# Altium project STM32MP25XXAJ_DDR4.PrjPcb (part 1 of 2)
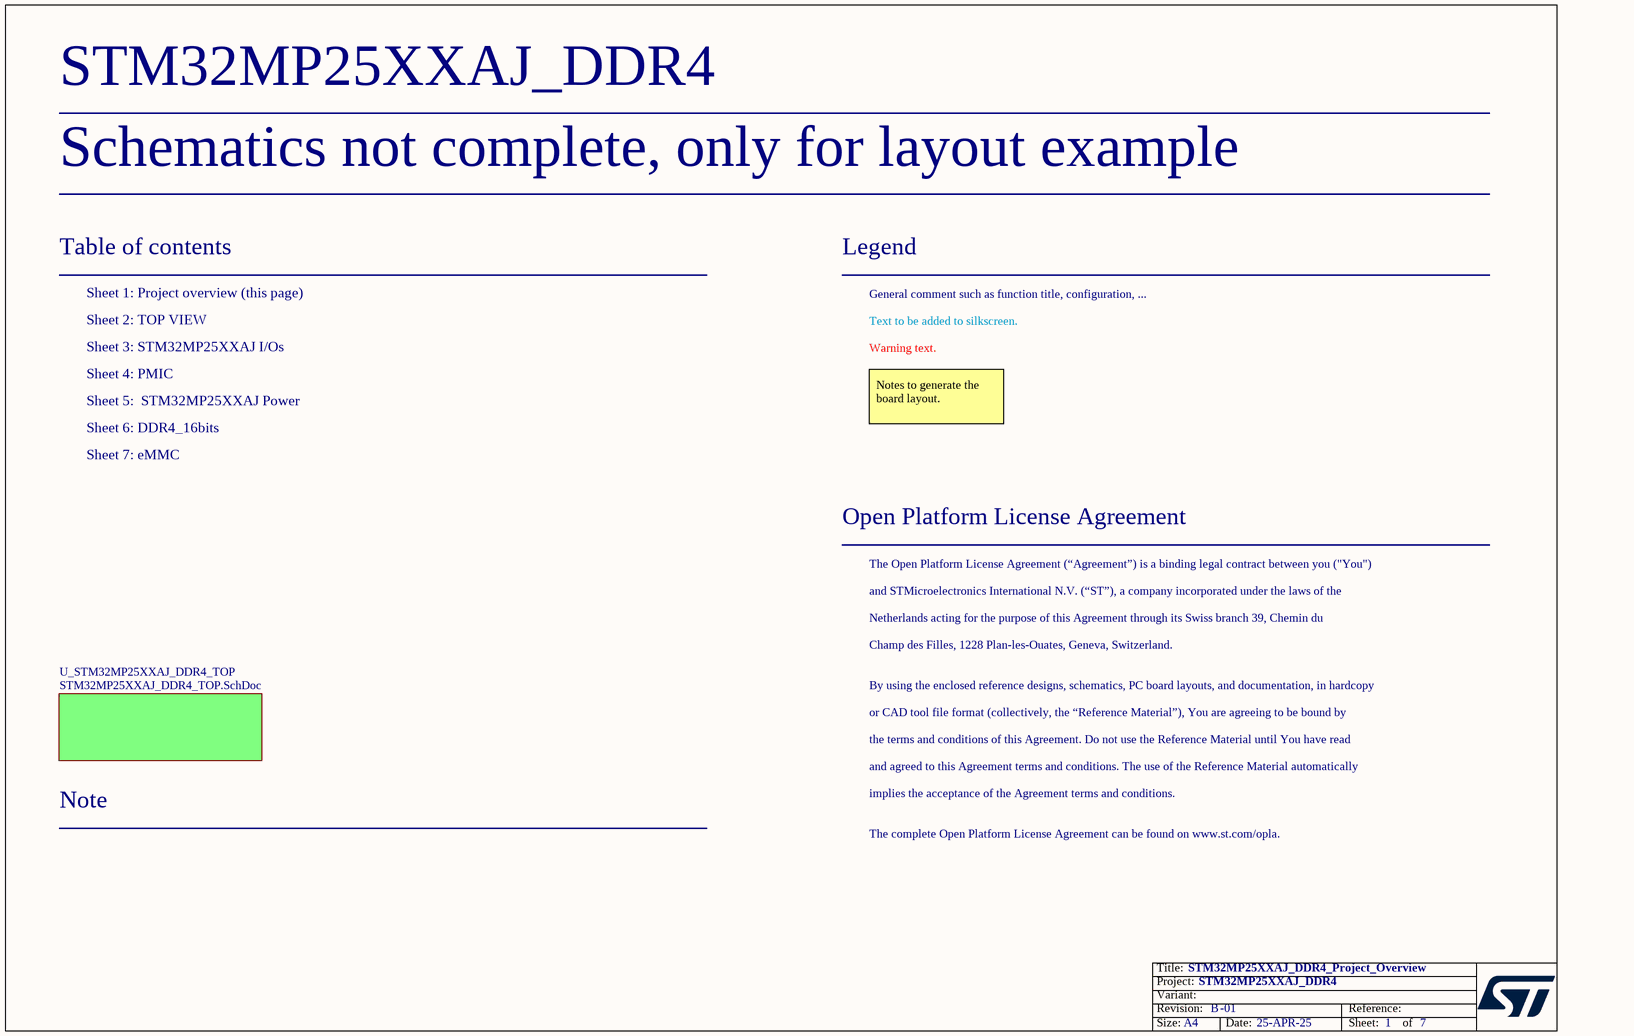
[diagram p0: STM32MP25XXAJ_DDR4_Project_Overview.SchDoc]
Board_Assembly_Revision: 01; Board_Document_Date: 25-APR-25; Board_Name: STM32MP25XXAJ_DDR4; Board_PCB_Revision: B
7 sheets, 226 parts. Net scope: flat (ports and power ports of the same name join across sheets).
Board file: STM32MP25XXAJ_DDR4.PcbDoc
Sheets:
  STM32MP25XXAJ_DDR4_Project_Overview.SchDoc
    U_STM32MP25XXAJ_DDR4_TOP = STM32MP25XXAJ_DDR4_TOP.SchDoc
      U_STM32MP25XXAJ I_Os = STM32MP25XXAJ I_Os.SchDoc
      U_PMIC = PMIC.SchDoc
      U_STM32MP25XXAJ Power = STM32MP25XXAJ Power.SchDoc
      U_eMMC = eMMC.SchDoc
      U_DDR4_16bits = DDR4_16bits.SchDoc

## Sheet STM32MP25XXAJ_DDR4_Project_Overview.SchDoc: STM32MP25XXAJ_DDR4_Project_Overview
size A4; Date: Not used; ApprovedBy: Not used; CheckedBy: Not used; Author: Not used; CompanyName: STMicroelectronics; DrawnBy: Not used; Engineer: Not used; Organization: Not used; Address1: Not used; Address2: Not used; Address3: Not used; Address4: Not used; DocumentNumber: 1; Revision: Not used; SheetNumber: 1; SheetTotal: 7

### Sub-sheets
U_STM32MP25XXAJ_DDR4_TOP = STM32MP25XXAJ_DDR4_TOP.SchDoc: no entries

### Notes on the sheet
- Schematics not complete, only for layout example
- Table of contents
- Sheet 1: Project overview (this page)
- Legend
- General comment such as function title, configuration, ...
- Sheet 2: TOP VIEW
- Sheet 3: STM32MP25XXAJ I/Os
- Sheet 4: PMIC
- Text to be added to silkscreen.
- Warning text.
- Sheet 5:  STM32MP25XXAJ Power
- Sheet 6: DDR4_16bits
- Notes to generate the board layout.
- Sheet 7: eMMC
- Open Platform License Agreement
- The Open Platform License Agreement (“Agreement”) is a binding legal contract between you ("You")
- and STMicroelectronics International N.V. (“ST”), a company incorporated under the laws of the
- Netherlands acting for the purpose of this Agreement through its Swiss branch 39, Chemin du
- Champ des Filles, 1228 Plan-les-Ouates, Geneva, Switzerland.
- By using the enclosed reference designs, schematics, PC board layouts, and documentation, in hardcopy
- or CAD tool file format (collectively, the “Reference Material”), You are agreeing to be bound by
- the terms and conditions of this Agreement. Do not use the Reference Material until You have read
- and agreed to this Agreement terms and conditions. The use of the Reference Material automatically
- Note
- implies the acceptance of the Agreement terms and conditions.
- The complete Open Platform License Agreement can be found on www.st.com/opla.

## Sheet STM32MP25XXAJ_DDR4_TOP.SchDoc: TOP
size A4; Date: Not used; ApprovedBy: Not used; CheckedBy: Not used; Author: Not used; CompanyName: STMicroelectronics; DrawnBy: Not used; Engineer: Not used; Organization: Not used; Address1: Not used; Address2: Not used; Address3: Not used; Address4: Not used; DocumentNumber: 2; Revision: Not used; SheetNumber: 2; SheetTotal: 7
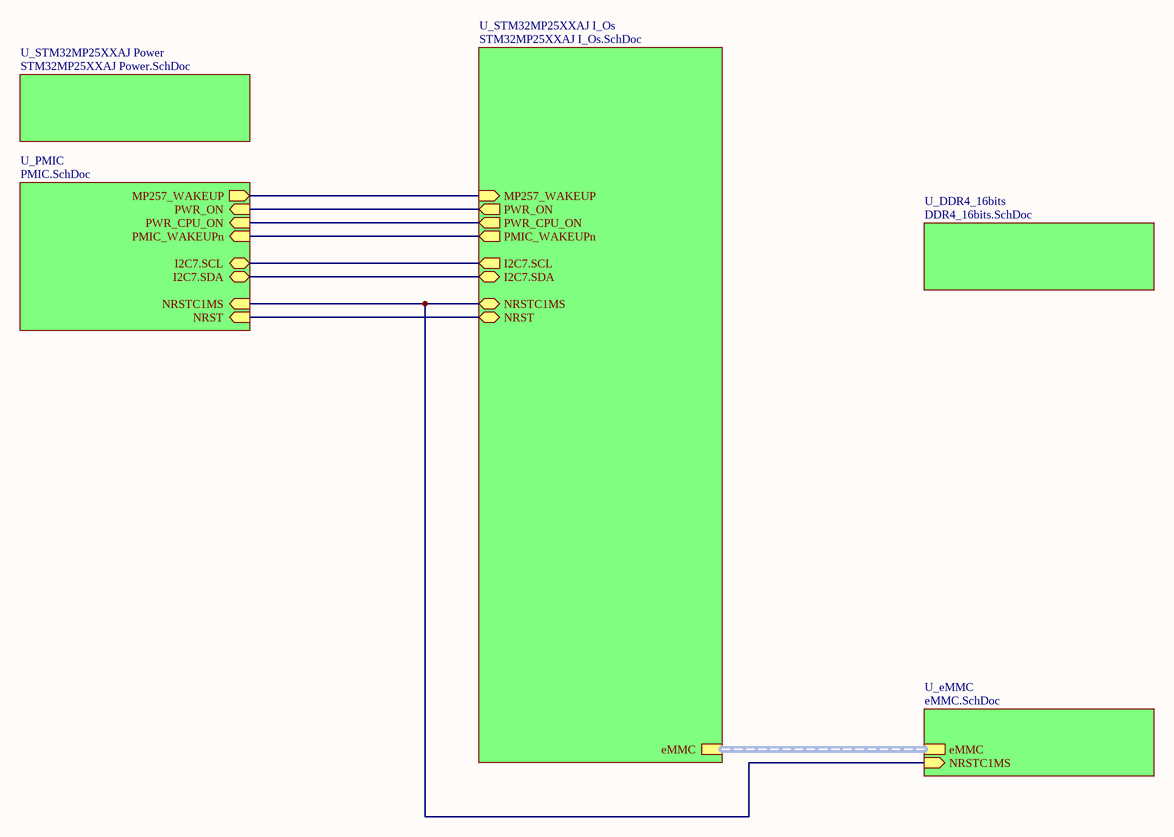
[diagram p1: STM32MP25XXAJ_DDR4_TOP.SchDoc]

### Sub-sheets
U_DDR4_16bits = DDR4_16bits.SchDoc: no entries
U_eMMC = eMMC.SchDoc: eMMC (harness eMMC), NRSTC1MS (in)
U_PMIC = PMIC.SchDoc: PMIC_WAKEUPn (in), NRST (in), I2C7.SCL (bidir), PWR_ON (in), PWR_CPU_ON (in), NRSTC1MS (in), I2C7.SDA (bidir), MP257_WAKEUP (out)
U_STM32MP25XXAJ I_Os = STM32MP25XXAJ I_Os.SchDoc: NRST (bidir), PWR_ON (out), NRSTC1MS (bidir), I2C7.SDA (bidir), I2C7.SCL (out), PWR_CPU_ON (out), MP257_WAKEUP (in), PMIC_WAKEUPn (out), eMMC (harness eMMC)
U_STM32MP25XXAJ Power = STM32MP25XXAJ Power.SchDoc: no entries

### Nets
(unnamed): sheet U_STM32MP25XXAJ I_Os/NRST, sheet U_PMIC/NRST
(unnamed): sheet U_STM32MP25XXAJ I_Os/PWR_ON, sheet U_PMIC/PWR_ON  [a separate net that carries the same name]
(unnamed): sheet U_STM32MP25XXAJ I_Os/NRSTC1MS, sheet U_PMIC/NRSTC1MS, sheet U_eMMC/NRSTC1MS  [a separate net that carries the same name]
(unnamed): sheet U_STM32MP25XXAJ I_Os/I2C7.SDA, sheet U_PMIC/I2C7.SDA  [a separate net that carries the same name]
(unnamed): sheet U_STM32MP25XXAJ I_Os/I2C7.SCL, sheet U_PMIC/I2C7.SCL  [a separate net that carries the same name]
(unnamed): sheet U_STM32MP25XXAJ I_Os/PWR_CPU_ON, sheet U_PMIC/PWR_CPU_ON  [a separate net that carries the same name]
(unnamed): sheet U_STM32MP25XXAJ I_Os/MP257_WAKEUP, sheet U_PMIC/MP257_WAKEUP  [a separate net that carries the same name]
(unnamed): sheet U_STM32MP25XXAJ I_Os/PMIC_WAKEUPn, sheet U_PMIC/PMIC_WAKEUPn  [a separate net that carries the same name]

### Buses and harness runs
harness sheet U_eMMC/eMMC = sheet U_STM32MP25XXAJ I_Os/eMMC

## Sheet STM32MP25XXAJ I_Os.SchDoc: STM32MP25XXAJ  I/Os
size A3; Date: Not used; ApprovedBy: Not used; CheckedBy: Not used; Author: Not used; CompanyName: STMicroelectronics; DrawnBy: Not used; Engineer: Not used; Organization: Not used; Address1: Not used; Address2: Not used; Address3: Not used; Address4: Not used; DocumentNumber: 3; Revision: Not used; SheetNumber: 3; SheetTotal: 7
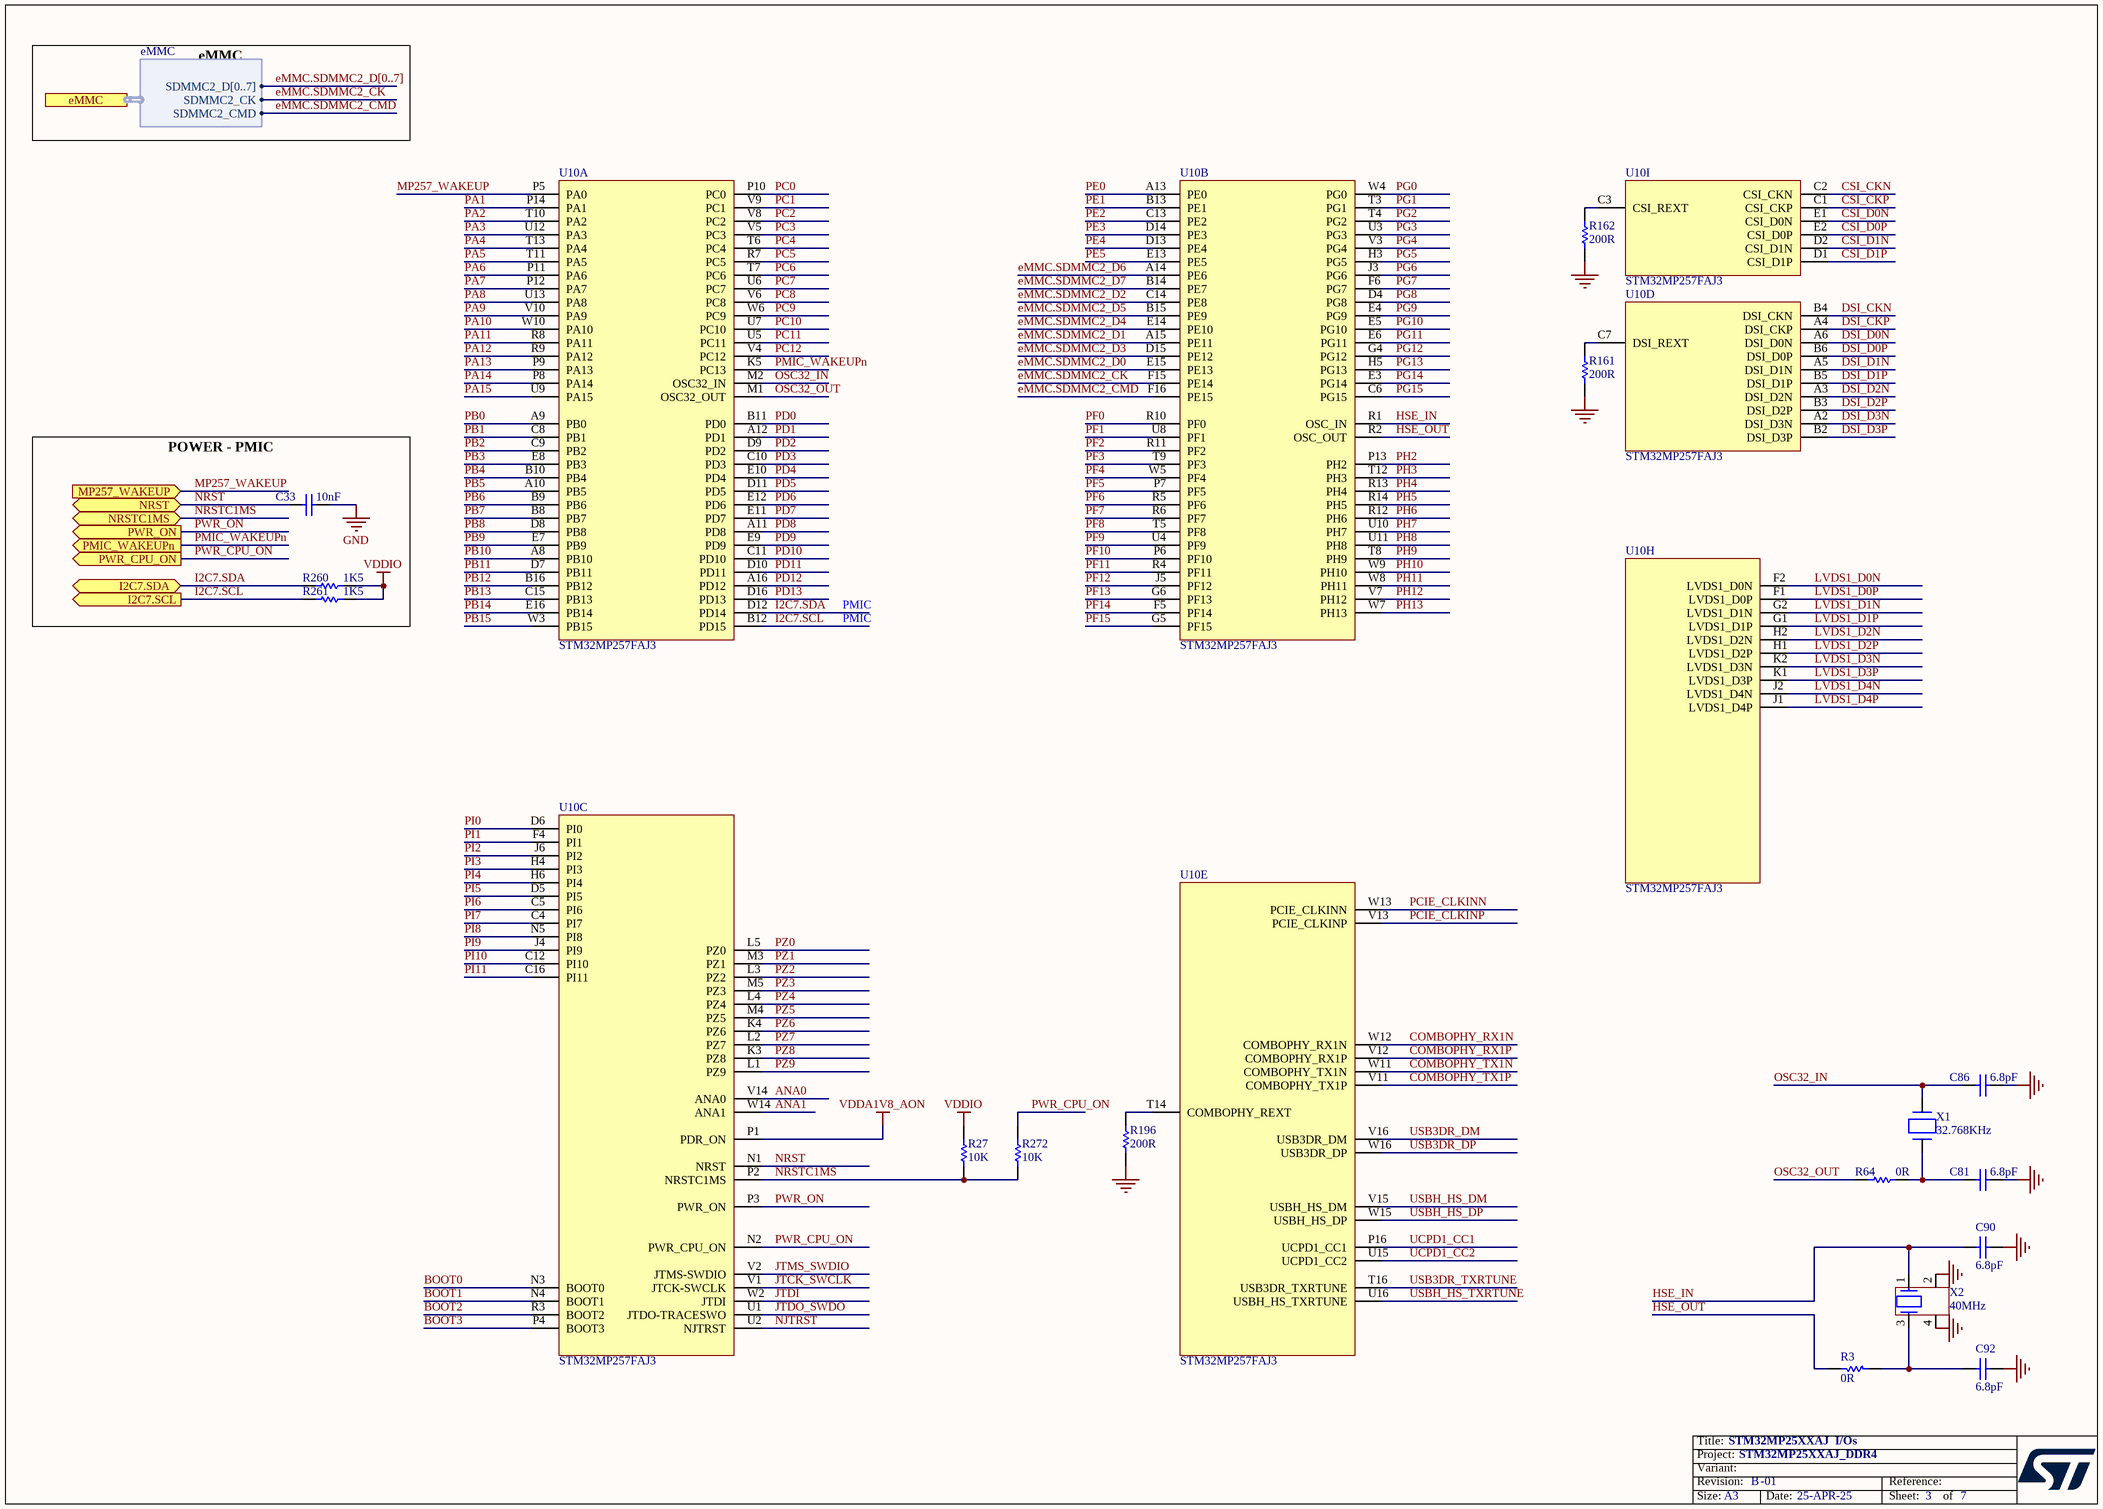
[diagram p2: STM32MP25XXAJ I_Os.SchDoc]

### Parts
C33  value 10nF  [C0402]  (hidden comment: Capacitor)
C81  value 6.8pF  [C0402]  (hidden comment: Capacitor)
C86  value 6.8pF  [C0402]  (hidden comment: Capacitor)
C90  value 6.8pF  [C0402]  (hidden comment: Capacitor)
C92  value 6.8pF  [C0402]  (hidden comment: Capacitor)
R3  value 0R  [R0402]
R27  value 10K  [R0402]  (hidden comment: Resistor)
R64  value 0R  [R0402]
R161  value 200R  [R0402]  (hidden comment: Resistor)
R162  value 200R  [R0402]  (hidden comment: Resistor)
R196  value 200R  [R0402]  (hidden comment: Resistor)
R260  value 1K5  [R0402]  (hidden comment: Resistor)
R261  value 1K5  [R0402]  (hidden comment: Resistor)
R272  value 10K  [R0402]  (hidden comment: Resistor)
U10  value STM32MP257FAJ3  [ICC_TFBGA361_16X16_P080]  (hidden comment: IC_STM32MP257FAJ3)  (parts A,B,C,D,E,H,I of 9)
X1  value 32.768KHz  [CRY_NX2012SA_2P]  (hidden comment: XTAL_2_PINS)
X2  value 40MHz  [CRY_NX1612SA_4P]  (hidden comment: XTAL_4_PINS)

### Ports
eMMC (harness eMMC), I2C7.SCL (out), I2C7.SDA (bidir), MP257_WAKEUP (in), NRST (bidir), NRSTC1MS (bidir), PMIC_WAKEUPn (out), PWR_CPU_ON (out), PWR_ON (out)

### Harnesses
eMMC: SDMMC2_CK, SDMMC2_CMD, SDMMC2_D[0..7]

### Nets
GND: C33.1 C81.2 C86.2 C90.1 C92.2 R161.2 R162.2 R196.1 X2.2 X2.4
VDDA1V8_AON: U10.P1(PDR_ON)
VDDIO: R27.2 R260.2 R261.2
ANA0: U10.V14(ANA0)
ANA1: U10.W14(ANA1)
BOOT0: U10.N3(BOOT0)
BOOT1: U10.N4(BOOT1)
BOOT2: U10.R3(BOOT2)
BOOT3: U10.P4(BOOT3)
COMBOPHY_RX1N: U10.W12(COMBOPHY_RX1N)
COMBOPHY_RX1P: U10.V12(COMBOPHY_RX1P)
COMBOPHY_TX1N: U10.W11(COMBOPHY_TX1N)
COMBOPHY_TX1P: U10.V11(COMBOPHY_TX1P)
CSI_CKN: U10.C2(CSI_CKN)
CSI_CKP: U10.C1(CSI_CKP)
CSI_D0N: U10.E1(CSI_D0N)
CSI_D0P: U10.E2(CSI_D0P)
CSI_D1N: U10.D2(CSI_D1N)
CSI_D1P: U10.D1(CSI_D1P)
DSI_CKN: U10.B4(DSI_CKN)
DSI_CKP: U10.A4(DSI_CKP)
DSI_D0N: U10.A6(DSI_D0N)
DSI_D0P: U10.B6(DSI_D0P)
DSI_D1N: U10.A5(DSI_D1N)
DSI_D1P: U10.B5(DSI_D1P)
DSI_D2N: U10.A3(DSI_D2N)
DSI_D2P: U10.B3(DSI_D2P)
DSI_D3N: U10.A2(DSI_D3N)
DSI_D3P: U10.B2(DSI_D3P)
eMMC.SDMMC2_CK: U10.F15(PE14) ; port eMMC.SDMMC2_CK
eMMC.SDMMC2_CMD: U10.F16(PE15) ; port eMMC.SDMMC2_CMD
eMMC.SDMMC2_D0: U10.E15(PE13)
eMMC.SDMMC2_D1: U10.A15(PE11)
eMMC.SDMMC2_D2: U10.C14(PE8)
eMMC.SDMMC2_D3: U10.D15(PE12)
eMMC.SDMMC2_D4: U10.E14(PE10)
eMMC.SDMMC2_D5: U10.B15(PE9)
eMMC.SDMMC2_D6: U10.A14(PE6)
eMMC.SDMMC2_D7: U10.B14(PE7)
HSE_IN: C90.2 U10.R1(OSC_IN) X2.1
HSE_OUT: R3.2 U10.R2(OSC_OUT)
I2C7.SCL: R261.1 U10.B12(PD15) ; port I2C7.SCL
I2C7.SDA: R260.1 U10.D12(PD14) ; port I2C7.SDA
JTCK_SWCLK: U10.V1(JTCK-SWCLK)
JTDI: U10.W2(JTDI)
JTDO_SWDO: U10.U1(JTDO-TRACESWO)
JTMS_SWDIO: U10.V2(JTMS-SWDIO)
LVDS1_D0N: U10.F2(LVDS1_D0N)
LVDS1_D0P: U10.F1(LVDS1_D0P)
LVDS1_D1N: U10.G2(LVDS1_D1N)
LVDS1_D1P: U10.G1(LVDS1_D1P)
LVDS1_D2N: U10.H2(LVDS1_D2N)
LVDS1_D2P: U10.H1(LVDS1_D2P)
LVDS1_D3N: U10.K2(LVDS1_D3N)
LVDS1_D3P: U10.K1(LVDS1_D3P)
LVDS1_D4N: U10.J2(LVDS1_D4N)
LVDS1_D4P: U10.J1(LVDS1_D4P)
MP257_WAKEUP: U10.P5(PA0) ; port MP257_WAKEUP
NJTRST: U10.U2(NJTRST)
NRST: C33.2 U10.N1(NRST) ; port NRST
NRSTC1MS: R27.1 R272.1 U10.P2(NRSTC1MS) ; port NRSTC1MS
OSC32_IN: C86.1 U10.M2(OSC32_IN) X1.2(X2)
OSC32_OUT: R64.1 U10.M1(OSC32_OUT)
PA1: U10.P14(PA1)
PA2: U10.T10(PA2)
PA3: U10.U12(PA3)
PA4: U10.T13(PA4)
PA5: U10.T11(PA5)
PA6: U10.P11(PA6)
PA7: U10.P12(PA7)
PA8: U10.U13(PA8)
PA9: U10.V10(PA9)
PA10: U10.W10(PA10)
PA11: U10.R8(PA11)
PA12: U10.R9(PA12)
PA13: U10.P9(PA13)
PA14: U10.P8(PA14)
PA15: U10.U9(PA15)
PB0: U10.A9(PB0)
PB1: U10.C8(PB1)
PB2: U10.C9(PB2)
PB3: U10.E8(PB3)
PB4: U10.B10(PB4)
PB5: U10.A10(PB5)
PB6: U10.B9(PB6)
PB7: U10.B8(PB7)
PB8: U10.D8(PB8)
PB9: U10.E7(PB9)
PB10: U10.A8(PB10)
PB11: U10.D7(PB11)
PB12: U10.B16(PB12)
PB13: U10.C15(PB13)
PB14: U10.E16(PB14)
PB15: U10.W3(PB15)
PC0: U10.P10(PC0)
PC1: U10.V9(PC1)
PC2: U10.V8(PC2)
PC3: U10.V5(PC3)
PC4: U10.T6(PC4)
PC5: U10.R7(PC5)
PC6: U10.T7(PC6)
PC7: U10.U6(PC7)
PC8: U10.V6(PC8)
PC9: U10.W6(PC9)
PC10: U10.U7(PC10)
PC11: U10.U5(PC11)
PC12: U10.V4(PC12)
PCIE_CLKINN: U10.W13(PCIE_CLKINN)
PCIE_CLKINP: U10.V13(PCIE_CLKINP)
PD0: U10.B11(PD0)
PD1: U10.A12(PD1)
PD2: U10.D9(PD2)
PD3: U10.C10(PD3)
PD4: U10.E10(PD4)
PD5: U10.D11(PD5)
PD6: U10.E12(PD6)
PD7: U10.E11(PD7)
PD8: U10.A11(PD8)
PD9: U10.E9(PD9)
PD10: U10.C11(PD10)
PD11: U10.D10(PD11)
PD12: U10.A16(PD12)
PD13: U10.D16(PD13)
PE0: U10.A13(PE0)
PE1: U10.B13(PE1)
PE2: U10.C13(PE2)
PE3: U10.D14(PE3)
PE4: U10.D13(PE4)
PE5: U10.E13(PE5)
PF0: U10.R10(PF0)
PF1: U10.U8(PF1)
PF2: U10.R11(PF2)
PF3: U10.T9(PF3)
PF4: U10.W5(PF4)
PF5: U10.P7(PF5)
PF6: U10.R5(PF6)
PF7: U10.R6(PF7)
PF8: U10.T5(PF8)
PF9: U10.U4(PF9)
PF10: U10.P6(PF10)
PF11: U10.R4(PF11)
PF12: U10.J5(PF12)
PF13: U10.G6(PF13)
PF14: U10.F5(PF14)
PF15: U10.G5(PF15)
PG0: U10.W4(PG0)
PG1: U10.T3(PG1)
PG2: U10.T4(PG2)
PG3: U10.U3(PG3)
PG4: U10.V3(PG4)
PG5: U10.H3(PG5)
PG6: U10.J3(PG6)
PG7: U10.F6(PG7)
PG8: U10.D4(PG8)
PG9: U10.E4(PG9)
PG10: U10.E5(PG10)
PG11: U10.E6(PG11)
PG12: U10.G4(PG12)
PG13: U10.H5(PG13)
PG14: U10.E3(PG14)
PG15: U10.C6(PG15)
PH2: U10.P13(PH2)
PH3: U10.T12(PH3)
PH4: U10.R13(PH4)
PH5: U10.R14(PH5)
PH6: U10.R12(PH6)
PH7: U10.U10(PH7)
PH8: U10.U11(PH8)
PH9: U10.T8(PH9)
PH10: U10.W9(PH10)
PH11: U10.W8(PH11)
PH12: U10.V7(PH12)
PH13: U10.W7(PH13)
PI0: U10.D6(PI0)
PI1: U10.F4(PI1)
PI2: U10.J6(PI2)
PI3: U10.H4(PI3)
PI4: U10.H6(PI4)
PI5: U10.D5(PI5)
PI6: U10.C5(PI6)
PI7: U10.C4(PI7)
PI8: U10.N5(PI8)
PI9: U10.J4(PI9)
PI10: U10.C12(PI10)
PI11: U10.C16(PI11)
PMIC_WAKEUPn: U10.K5(PC13) ; port PMIC_WAKEUPn
PWR_CPU_ON: R272.2 U10.N2(PWR_CPU_ON) ; port PWR_CPU_ON
PWR_ON: U10.P3(PWR_ON) ; port PWR_ON
PZ0: U10.L5(PZ0)
PZ1: U10.M3(PZ1)
PZ2: U10.L3(PZ2)
PZ3: U10.M5(PZ3)
PZ4: U10.L4(PZ4)
PZ5: U10.M4(PZ5)
PZ6: U10.K4(PZ6)
PZ7: U10.L2(PZ7)
PZ8: U10.K3(PZ8)
PZ9: U10.L1(PZ9)
UCPD1_CC1: U10.P16(UCPD1_CC1)
UCPD1_CC2: U10.U15(UCPD1_CC2)
USB3DR_DM: U10.V16(USB3DR_DM)
USB3DR_DP: U10.W16(USB3DR_DP)
USB3DR_TXRTUNE: U10.T16(USB3DR_TXRTUNE)
USBH_HS_DM: U10.V15(USBH_HS_DM)
USBH_HS_DP: U10.W15(USBH_HS_DP)
USBH_HS_TXRTUNE: U10.U16(USBH_HS_TXRTUNE)
NetC81_1: C81.1 R64.2 X1.1(X1)
NetC92_1: C92.1 R3.1 X2.3
NetR161_1: R161.1 U10.C7(DSI_REXT)
NetR162_1: R162.1 U10.C3(CSI_REXT)
NetR196_2: R196.2 U10.T14(COMBOPHY_REXT)

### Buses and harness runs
bus eMMC.SDMMC2_D[0..7]

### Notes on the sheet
- eMMC
- POWER - PMIC
- PMIC

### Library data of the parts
C33 = MCD-00011: Capacitor, MLCC, 10nF, 16V, X7R, 10%, 0402, T=0.5mm; Manufacturer_Part_Number: CC0402KRX7R7BB103; Manufacturer: YAGEO; Provided_By: SUBCO; Initial_Board_Reference: MB1274
C81 C86 = MCD-00674: Capacitor, MLCC, 6.8pF, 50V, NPO, +-0.25pF, 0402, T=0.5mm; Manufacturer_Part_Number: CC0402CRNPO9BN6R8; Manufacturer: YAGEO; Part_Preference: Recommended; Provided_By: SUBCO; Initial_Board_Reference: MB1319; Path: ws/MCD_ApplicationBoards/Lists/MCDPARTSdatabase; Item Type: Item; Component_Country_Of_Origin: China; ID: 3068; ShowFields: YES
C90 C92 = MCD-00674: Capacitor, MLCC, 6.8pF, 50V, NPO, +-0.25pF, 0402, T=0.5mm; Manufacturer_Part_Number: CC0402CRNPO9BN6R8; Manufacturer: YAGEO; Part_Preference: Recommended; Provided_By: SUBCO; Initial_Board_Reference: MB1319; Component_Country_Of_Origin: China; ID: 3068; ShowFields: YES
R3 R64 = MCD-00052: Resistor,0R,0402,5%,1/16W; Manufacturer_Part_Number: RC0402JR-070RL; Manufacturer: YAGEO; Part_Preference: Recommended; Provided_By: SUBCO; Initial_Board_Reference: mb1274; Order_Code_RS: 618-5804; Component_Country_Of_Origin: China; ID: 2540; ShowFields: YES
R27 R272 = MCD-00053: Resistor,10K,0402,1%,1/16W; BMS_Part_Number: 9131590; Part_Preference: Recommended; Manufacturer: YAGEO; Manufacturer_Part_Number: RC0402FR-0710KL; Component_Country_Of_Origin: China; ID: 2539; ShowFields: YES
R161 R162 = MCD-00417: Resistor,200R,0402,1%,1/16W; Manufacturer_Part_Number: RC0402FR-07200RL; Manufacturer: YAGEO; Part_Preference: Recommended; ECCN_US: EAR99; ECCN_EU: NEC; Provided_By: SUBCO
R196 = MCD-00417: Resistor,200R,0402,1%,1/16W; Part_Preference: Recommended; Manufacturer: YAGEO; Manufacturer_Part_Number: RC0402FR-07200RL
R260 R261 = MCD-00068: Resistor,1K5,0402,1%,1/16W; Part_Preference: Recommended; Manufacturer: YAGEO; Manufacturer_Part_Number: RC0402FR-071K5L; Component_Country_Of_Origin: China; ID: 2524; ShowFields: YES
U10 = MCD-04441: MPU, Dual Core ARM cortex-A35 64-bit + M33 32-bit,  808KB SRAM, With Crypto; Part_Type: IC; Part_Preference: Recommended; Manufacturer: STMICROELECTRONICS; ShowFields: YES; ID: 6557
X1 = MCD-01479: Crystal, 32.768kHz, 6pF, +/-20ppm, 80K, 2.05x1.2mm; BMS_Part_Number: 9157049; Part_Type: Crystal_Osc; Part_Preference: Recommended; Manufacturer: NDK; Manufacturer_Part_Number: NX2012SA-32.768KHZ-EXS00A-MU00527; Component_Country_Of_Origin: Unknown; ShowFields: YES; ID: 3579
X2 = MCD-02344: Crystal, 40MHz, 6pF, +/-20ppm, 80R, 1.6x1.2mm; Part_Type: Crystal_Osc; Part_Preference: Recommended; Manufacturer: NDK; Manufacturer_Part_Number: NX1612SA-40MHZ-EXS00A-CS13836; Component_Country_Of_Origin: Unknown; ShowFields: YES; ID: 4450

## Sheet PMIC.SchDoc: PMIC
size A3; Date: Not used; ApprovedBy: Not used; CheckedBy: Not used; Author: Not used; CompanyName: STMicroelectronics; DrawnBy: Not used; Engineer: Not used; Organization: Not used; Address1: Not used; Address2: Not used; Address3: Not used; Address4: Not used; DocumentNumber: 4; Revision: Not used; SheetNumber: 4; SheetTotal: 7
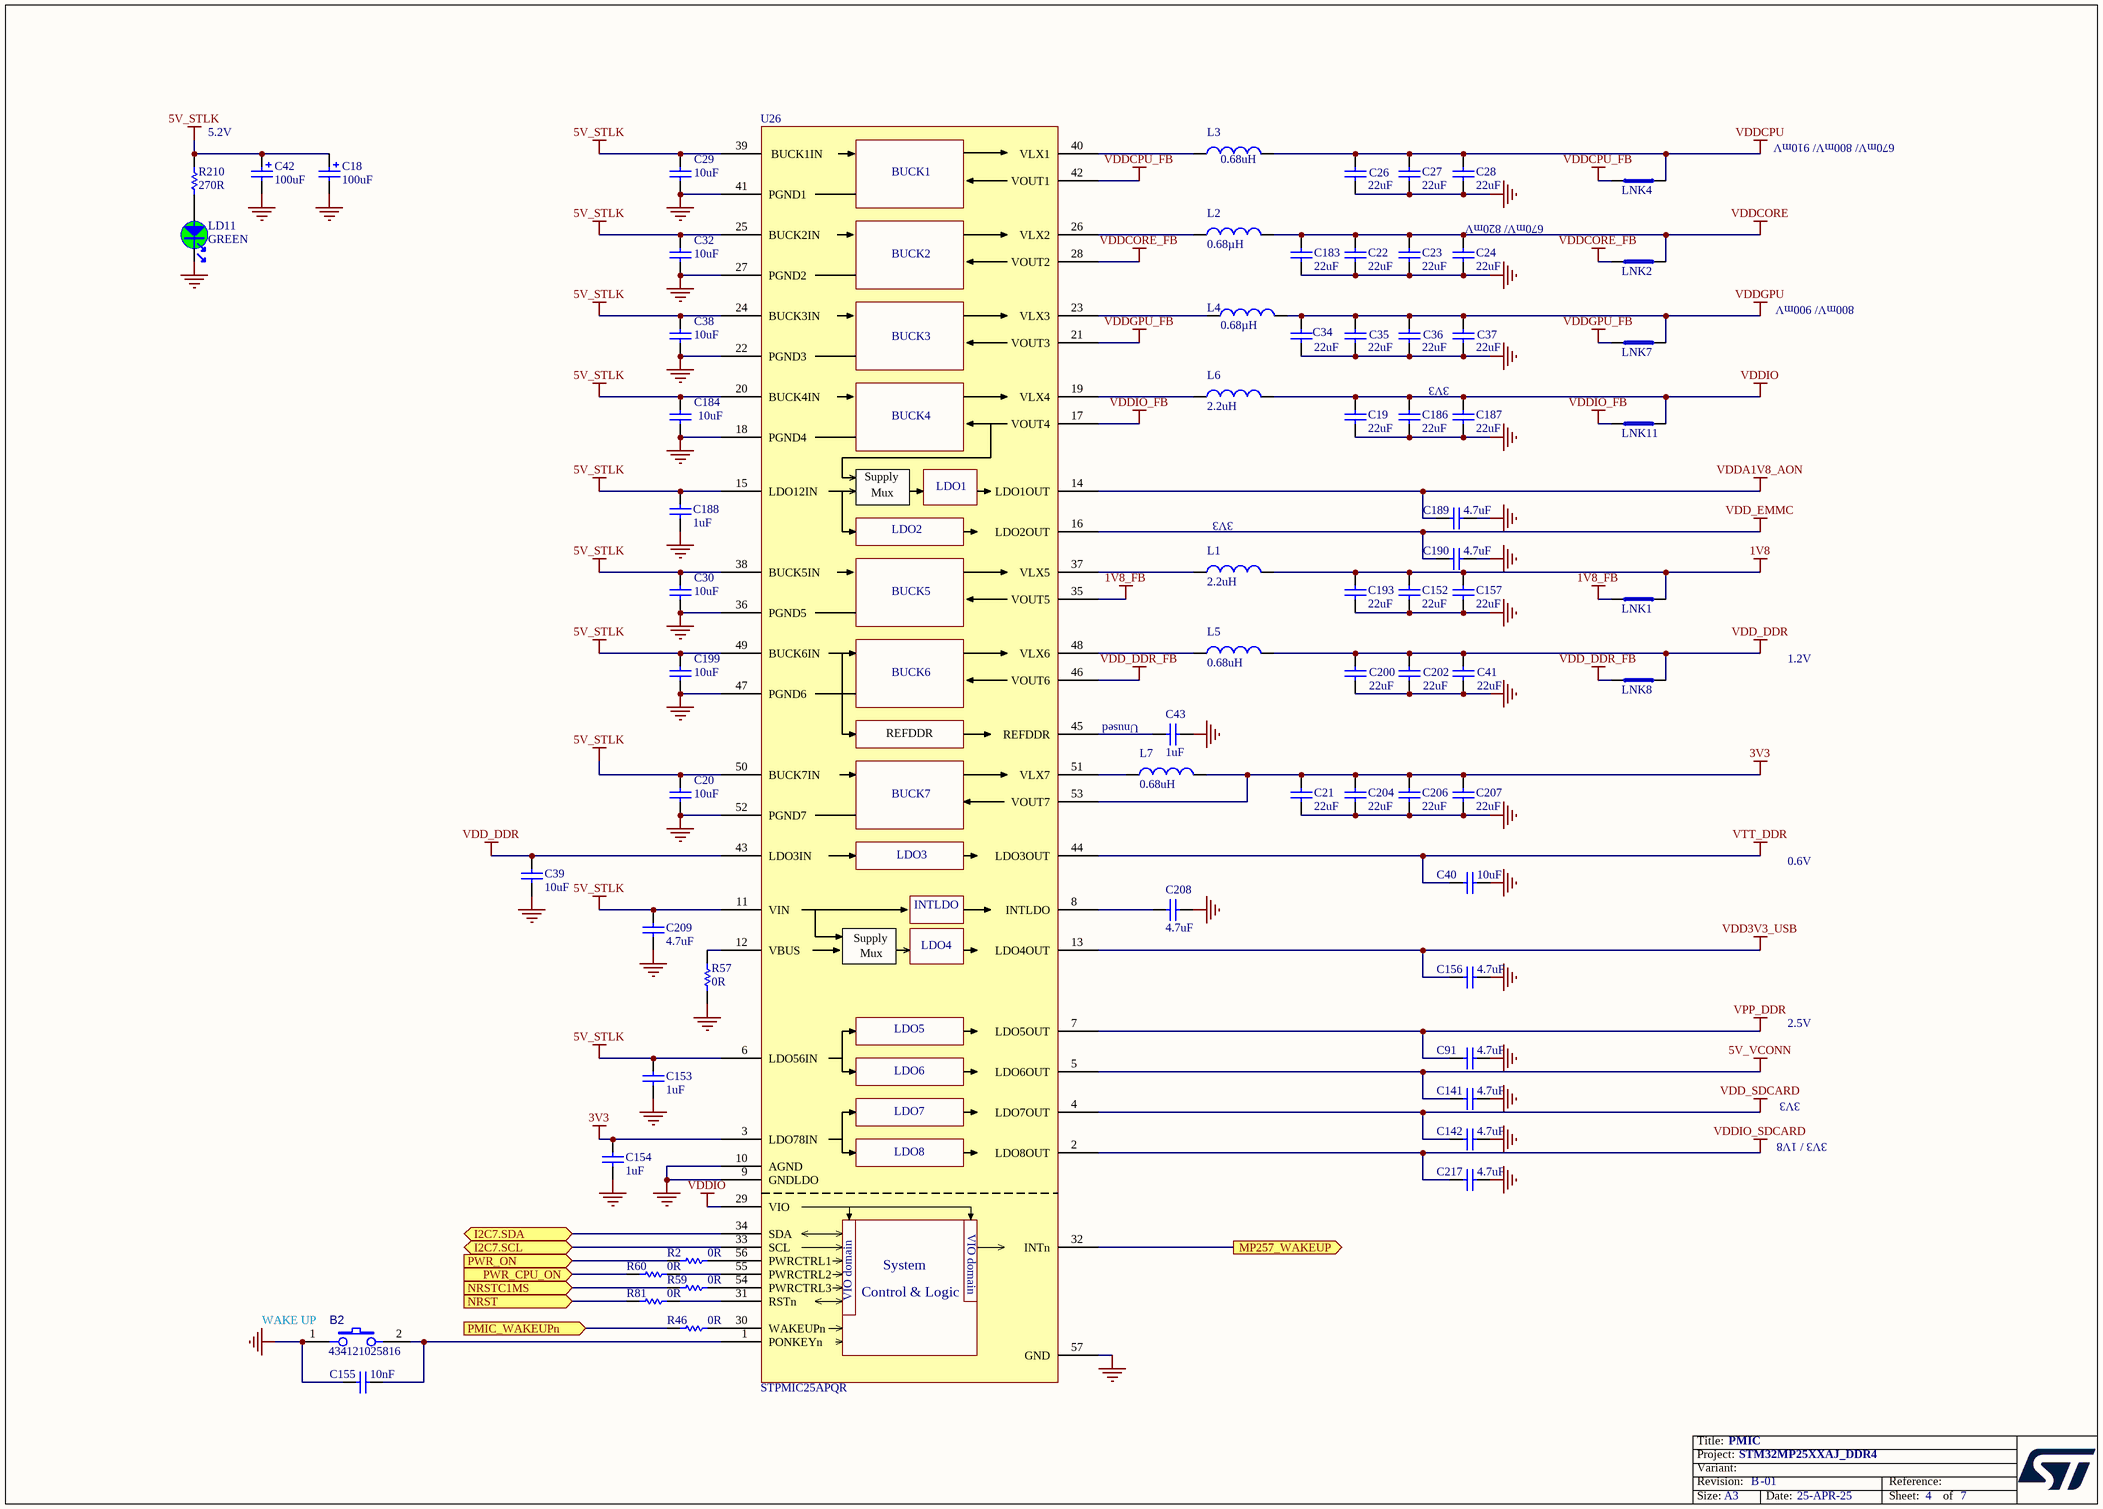
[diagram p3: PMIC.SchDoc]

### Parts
B2  value 434121025816  [SWI_WE_434121025816]  (hidden comment: SW_PUSH_SMD_2P)
C18  value 100uF  [CPOL_TCJ-B_1210_H210]  (hidden comment: Cap_POL_TANA)
C19  value 22uF  [C0805]  (hidden comment: Capacitor)
C20  value 10uF  [C0603]  (hidden comment: Capacitor)
C21  value 22uF  [C0805]  (hidden comment: Capacitor)
C22  value 22uF  [C0603]  (hidden comment: Capacitor)
C23  value 22uF  [C0603]  (hidden comment: Capacitor)
C24  value 22uF  [C0603]  (hidden comment: Capacitor)
C26  value 22uF  [C0603]  (hidden comment: Capacitor)
C27  value 22uF  [C0603]  (hidden comment: Capacitor)
C28  value 22uF  [C0603]  (hidden comment: Capacitor)
C29  value 10uF  [C0603]  (hidden comment: Capacitor)
C30  value 10uF  [C0603]  (hidden comment: Capacitor)
C32  value 10uF  [C0603]  (hidden comment: Capacitor)
C34  value 22uF  [C0603]  (hidden comment: Capacitor)
C35  value 22uF  [C0603]  (hidden comment: Capacitor)
C36  value 22uF  [C0603]  (hidden comment: Capacitor)
C37  value 22uF  [C0603]  (hidden comment: Capacitor)
C38  value 10uF  [C0603]  (hidden comment: Capacitor)
C39  value 10uF  [C0402]  (hidden comment: Capacitor)
C40  value 10uF  [C0402]  (hidden comment: Capacitor)
C41  value 22uF  [C0603]  (hidden comment: Capacitor)
C42  value 100uF  [CPOL_TCJ-B_1210_H210]  (hidden comment: Cap_POL_TANA)
C43  value 1uF  [C0402]  (hidden comment: Capacitor)
C91  value 4.7uF  [C0402]  (hidden comment: Capacitor)
C141  value 4.7uF  [C0402]  (hidden comment: Capacitor)
C142  value 4.7uF  [C0402]  (hidden comment: Capacitor)
C152  value 22uF  [C0805]  (hidden comment: Capacitor)
C153  value 1uF  [C0402]  (hidden comment: Capacitor)
C154  value 1uF  [C0402]  (hidden comment: Capacitor)
C155  value 10nF  [C0402]  (hidden comment: Capacitor)
C156  value 4.7uF  [C0402]  (hidden comment: Capacitor)
C157  value 22uF  [C0805]  (hidden comment: Capacitor)
C183  value 22uF  [C0603]  (hidden comment: Capacitor)
C184  value 10uF  [C0603]  (hidden comment: Capacitor)
C186  value 22uF  [C0805]  (hidden comment: Capacitor)
C187  value 22uF  [C0805]  (hidden comment: Capacitor)
C188  value 1uF  [C0402]  (hidden comment: Capacitor)
C189  value 4.7uF  [C0402]  (hidden comment: Capacitor)
C190  value 4.7uF  [C0402]  (hidden comment: Capacitor)
C193  value 22uF  [C0805]  (hidden comment: Capacitor)
C199  value 10uF  [C0603]  (hidden comment: Capacitor)
C200  value 22uF  [C0603]  (hidden comment: Capacitor)
C202  value 22uF  [C0603]  (hidden comment: Capacitor)
C204  value 22uF  [C0805]  (hidden comment: Capacitor)
C206  value 22uF  [C0805]  (hidden comment: Capacitor)
C207  value 22uF  [C0805]  (hidden comment: Capacitor)
C208  value 4.7uF  [C0402]  (hidden comment: Capacitor)
C209  value 4.7uF  [C0402]  (hidden comment: Capacitor)
C217  value 4.7uF  [C0402]  (hidden comment: Capacitor)
L1  value 2.2uH  [IND_2016_MURATA_LQM2MPN2R2NG0]  (hidden comment: Inductor)
L2  value 0.68µH  [IND_2520_TOKO_DFE252012P]  (hidden comment: Inductor)
L3  value 0.68uH  [IND_2016_MURATA_LQM2MPN2R2NG0]  (hidden comment: Inductor)
L4  value 0.68µH  [IND_2520_TOKO_DFE252012P]  (hidden comment: Inductor)
L5  value 0.68uH  [IND_2016_MURATA_LQM2MPN2R2NG0]  (hidden comment: Inductor)
L6  value 2.2uH  [IND_2016_MURATA_LQM2MPN2R2NG0]  (hidden comment: Inductor)
L7  value 0.68uH  [IND_2016_MURATA_LQM2MPN2R2NG0]  (hidden comment: Inductor)
LD11  value GREEN  [LED_0603_OSRAM_LG-Q396-PS-35_GREEN_1A2K_H0P4]  (hidden comment: LED_green)
LNK1  link_200  [LINK200]  (value not drawn)  (no BOM)
LNK2  link_200  [LINK200]  (value not drawn)  (no BOM)
LNK4  link_200  [LINK200]  (value not drawn)  (no BOM)
LNK7  link_200  [LINK200]  (value not drawn)  (no BOM)
LNK8  link_200  [LINK200]  (value not drawn)  (no BOM)
LNK11  link_200  [LINK200]  (value not drawn)  (no BOM)
R2  value 0R  [R0402]
R46  value 0R  [R0402]
R57  value 0R  [R0402]
R59  value 0R  [R0402]
R60  value 0R  [R0402]
R81  value 0R  [R0402]
R210  value 270R  [R0402]  (hidden comment: Resistor)
U26  STPMIC25APQR  [ICC_QFN56-EPAD_6P5X6P5_P040]

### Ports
I2C7.SCL (bidir), I2C7.SDA (bidir), MP257_WAKEUP (out), NRST (in), NRSTC1MS (in), PMIC_WAKEUPn (in), PWR_CPU_ON (in), PWR_ON (in)

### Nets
1V8: C152.2 C157.2 C193.2 L1.2 LNK1.2
1V8_FB: LNK1.1 U26.35(VOUT5)
3V3: C21.2 C154.2 C204.2 C206.2 C207.2 L7.2 U26.3(LDO78IN) U26.53(VOUT7)
5V_STLK: C18.1 C20.2 C29.2 C30.2 C32.2 C38.2 C42.1 C153.2 C184.2 C188.2 C199.2 C209.2 R210.1 U26.6(LDO56IN) U26.11(VIN) U26.15(LDO12IN) U26.20(BUCK4IN) U26.24(BUCK3IN) U26.25(BUCK2IN) U26.38(BUCK5IN) U26.39(BUCK1IN) U26.49(BUCK6IN) U26.50(BUCK7IN)
5V_VCONN: C141.1 U26.5(LDO6OUT)
GND: B2.1 C18.2 C19.1 C20.1 C21.1 C22.1 C23.1 C24.1 C26.1 C27.1 C28.1 C29.1 C30.1 C32.1 C34.1 C35.1 C36.1 C37.1 C38.1 C39.1 C40.1 C41.1 C42.2 C43.1 C91.2 C141.2 C142.2 C152.1 C153.1 C154.1 C155.1 C156.1 C157.1 C183.1 C184.1 C186.1 C187.1 C188.1 C189.1 C190.2 C193.1 C199.1 C200.1 C202.1 C204.1 C206.1 C207.1 C208.2 C209.1 C217.2 LD11.2 R57.1 U26.9(GNDLDO) U26.10(AGND) U26.18(PGND4) U26.22(PGND3) U26.27(PGND2) U26.36(PGND5) U26.41(PGND1) U26.47(PGND6) U26.52(PGND7) U26.57(GND)
VDD3V3_USB: C156.2 U26.13(LDO4OUT)
VDD_DDR: C39.2 C41.2 C200.2 C202.2 L5.2 LNK8.2 U26.43(LDO3IN)
VDD_DDR_FB: LNK8.1 U26.46(VOUT6)
VDD_EMMC: C190.1 U26.16(LDO2OUT)
VDD_SDCARD: C142.1 U26.4(LDO7OUT)
VDDA1V8_AON: C189.2 U26.14(LDO1OUT)
VDDCORE: C22.2 C23.2 C24.2 C183.2 L2.2 LNK2.2
VDDCORE_FB: LNK2.1 U26.28(VOUT2)
VDDCPU: C26.2 C27.2 C28.2 L3.2 LNK4.1
VDDCPU_FB: LNK4.2 U26.42(VOUT1)
VDDGPU: C34.2 C35.2 C36.2 C37.2 L4.2 LNK7.2
VDDGPU_FB: LNK7.1 U26.21(VOUT3)
VDDIO: C19.2 C186.2 C187.2 L6.2 LNK11.2 U26.29(VIO)
VDDIO_FB: LNK11.1 U26.17(VOUT4)
VDDIO_SDCARD: C217.1 U26.2(LDO8OUT)
VPP_DDR: C91.1 U26.7(LDO5OUT)
VTT_DDR: C40.2 U26.44(LDO3OUT)
I2C7.SCL: U26.33(SCL) ; port I2C7.SCL
I2C7.SDA: U26.34(SDA) ; port I2C7.SDA
MP257_WAKEUP: U26.32(INTn) ; port MP257_WAKEUP
NRST: R81.1 ; port NRST
NRSTC1MS: R59.1 ; port NRSTC1MS
PMIC_WAKEUPn: R46.1 ; port PMIC_WAKEUPn
PWR_CPU_ON: R60.1 ; port PWR_CPU_ON
PWR_ON: R2.1 ; port PWR_ON
NetB2_2: B2.2 C155.2 U26.1(PONKEYn)
NetC43_2: C43.2 U26.45(REFDDR)
NetC208_1: C208.1 U26.8(INTLDO)
NetL1_1: L1.1 U26.37(VLX5)
NetL2_1: L2.1 U26.26(VLX2)
NetL3_1: L3.1 U26.40(VLX1)
NetL4_1: L4.1 U26.23(VLX3)
NetL5_1: L5.1 U26.48(VLX6)
NetL6_1: L6.1 U26.19(VLX4)
NetL7_1: L7.1 U26.51(VLX7)
NetLD11_1: LD11.1 R210.2
NetR2_2: R2.2 U26.56(PWRCTRL1)
NetR46_2: R46.2 U26.30(WAKEUPn)
NetR57_2: R57.2 U26.12(VBUS)
NetR59_2: R59.2 U26.54(PWRCTRL3)
NetR60_2: R60.2 U26.55(PWRCTRL2)
NetR81_2: R81.2 U26.31(RSTn)

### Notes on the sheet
- 5.2V
- 670mV/ 800mV/ 910mV
- (near C24) 670mV/ 820mV
- 800mV/ 900mV
- 3V3
- (near L1) 3V3
- Unused
- 1.2V
- 0.6V
- 2.5V
- 3V3 / 1V8
- (near B2) WAKE UP

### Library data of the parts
B2 = MCD-03492: Switch tactile, SPST-NO, 50mA, 12V, 6x3.8mm; Part_Type: Misc; Part_Preference: Recommended; Manufacturer: WURTH ELEKTRONIC; Component_Country_Of_Origin: China°; ShowFields: YES; ID: 5608
C18 C42 = MCD-01796: Capacitor, Tantalum, 100uF, 6V3, 40mR, +/-20%,  Type_B (3528 metric), T=1.9mm; Part_Preference: Recommended; Manufacturer: AVX; Manufacturer_Part_Number: TCJB107M006R0040; Component_Country_Of_Origin: Lanskroun; ShowFields: YES; ID: 3896
C19 C21 C152 C157 C186 C187 C193 C204 C206 C207 = MCD-03139: Capacitor, MLCC, 22uF, 10V, X5R, +/-20%, 0805, T=1,25mm; Part_Preference: Recommended; Manufacturer: MURATA; Manufacturer_Part_Number: GRM21BR61A226ME51L; ShowFields: YES; ID: 5255; Component_Country_Of_Origin: China, Japan
C20 C29 C30 C32 C38 C184 C199 = MCD-00099: Capacitor, MLCC, 10uF, 10V, X5R, +/-10%, 0603, T=0,8mm; Manufacturer_Part_Number: GRM188R61A106KE69D; Manufacturer: MURATA; Part_Preference: Recommended; Order_Code_RS: 170-6168; Component_Country_Of_Origin: Japan; ID: 2770; ShowFields: YES
C22-C24 C26 C34-C37 C41 C200 C202 = MCD-00100: Capacitor, MLCC, 22uF, 6V3, X5R, +/-20%, 0603, T=0,8mm; Manufacturer_Part_Number: GRM188R60J226MEA0J; Manufacturer: MURATA; Part_Preference: Recommended; Component_Country_Of_Origin: Japan; ID: 2766; ShowFields: YES
C27 C28 C183 = MCD-00100: Capacitor, MLCC, 22uF, 6V3, X5R, +/-20%, 0603, T=0,8mm; Part_Preference: Recommended; Manufacturer: MURATA; Manufacturer_Part_Number: GRM188R60J226MEA0J; Component_Country_Of_Origin: Japan; ID: 2766; ShowFields: YES
C39 = MCD-03140: Capacitor, MLCC, 10uF, 6.3V, X5R, +/-20%, 0402, T=0.5mm; Part_Preference: Recommended; Manufacturer: MURATA; Manufacturer_Part_Number: GRM155R60J106ME05D; ShowFields: YES; ID: 5256
C40 = MCD-03140: Capacitor, MLCC, 10uF, 6.3V, X5R, +/-20%, 0402, T=0.5mm; Part_Preference: Recommended; Manufacturer: MURATA; Manufacturer_Part_Number: GRM155R60J106ME05D; ShowFields: YES; ID: 5256; Component_Country_Of_Origin: China, Japan
C43 C153 C154 C188 = MCD-00095: Capacitor, MLCC, 1uF, 25V, X5R, +/-10%, 0402, T=0.5mm; Part_Preference: Recommended; Manufacturer: MURATA; Manufacturer_Part_Number: GRM155R61E105KA12; Order_Code_RS: 846-7287; Component_Country_Of_Origin: Japan; ShowFields: YES; ID: 2772
C91 C141 C142 C156 C189 C190 C208 C209 C217 = MCD-01356: Capacitor, MLCC, 4.7uF, 6V3, X5R, +/-20%, 0402, T=0.5mm; Manufacturer_Part_Number: GRM155R60J475ME47; Manufacturer: MURATA; Part_Preference: Recommended; Order_Code_RS: 814-5230; Component_Country_Of_Origin: Japan; ShowFields: YES; ID: 3456
C155 = MCD-02198: Capacitor, MLCC, 10nF, 50V, X7R, +/-10%, 0402, T=0.5mm; Manufacturer_Part_Number: CC0402KRX7R9BB103; Manufacturer: YAGEO; Part_Preference: Recommended; Order_Code_RS: 6169644; Component_Country_Of_Origin: China; ShowFields: YES; ID: 4298
L1 L6 = MCD-03143: Inductor, 2.2uH, +/-20%, Itemp= 1700mA, Isat= 2400mA, 0R140, 0806, T=1mm; Part_Preference: Recommended; Manufacturer: MURATA; Manufacturer_Part_Number: DFE201610E-2R2M=P2; ShowFields: YES; ID: 5259; Component_Country_Of_Origin: Vietnam
L2 L4 = MCD-03142: Inductor, 0.68uH, +/-20%, Itemp= 3900mA, Isat= 5400mA, 0R031, 1008, T=1.2mm; Part_Preference: Recommended; Manufacturer: MURATA; Manufacturer_Part_Number: DFE252012F-R68M=P2; ShowFields: YES; ID: 5258; Component_Country_Of_Origin: Vietnam
L3 L5 L7 = MCD-03141: Inductor, 0.68uH, +/-20%, Itemp= 3100mA, Isat= 4300mA, 0R043, 0806, T=1mm; Part_Preference: Recommended; Manufacturer: MURATA; Manufacturer_Part_Number: DFE201610E-R68M=P2; ShowFields: YES; ID: 5257; Component_Country_Of_Origin: Vietnam
LD11 = MCD-00588: LED Green, 0603 SMD, Forward Voltage Typ=2V, Max=2.5V; Part_Type: Display; Manufacturer_Part_Number: LG Q396-PS-35; Manufacturer: OSRAM OPTO SEMICONDUCTORS; Alternate_Manufacturer_Part_Number: VLMTG1300-GS08; Alternate_Manufacturer: VISHAY SEMICONDUCTOR OPTO DIVISION; Alternate_Internal_Part_Number: MCD-02400; Part_Preference: Recommended; Provided_By: SUBCO; Component_Country_Of_Origin: Unknown; ID: 3155; ShowFields: YES
LNK1 LNK2 LNK4 LNK7 LNK8 LNK11 = MCD-02777: Track link on PCB 200um width for layout routing; Part_Preference: Recommended; Part_Type: Misc; ID: 4889; ShowFields: YES
R2 R46 R57 R59 R60 R81 = MCD-00052: Resistor,0R,0402,5%,1/16W; Manufacturer_Part_Number: RC0402JR-070RL; Manufacturer: YAGEO; Part_Preference: Recommended; ECCN_US: EAR99; ECCN_EU: NEC; Provided_By: SUBCO; Initial_Board_Reference: mb1274; Order_Code_RS: 618-5804; Component_Country_Of_Origin: China; ID: 2540; ShowFields: YES
R210 = MCD-00441: Resistor,270R,0402,1%,1/16W; Manufacturer_Part_Number: RC0402FR-07270RL; Manufacturer: YAGEO; Part_Preference: Recommended; Provided_By: SUBCO; ECCN_US: EAR99; ECCN_EU: NEC; Component_Country_Of_Origin: China; ID: 2838; ShowFields: YES
U26 = MCD-03000: STPMIC2; Part_Type: IC; Part_Preference: Recommended; Manufacturer: STMICROELECTRONICS; Component_Country_Of_Origin: Unknown; ShowFields: YES; ID: 5116

## Sheet STM32MP25XXAJ Power.SchDoc: STM32MP25XXAJ Power
size A3; Date: Not used; ApprovedBy: Not used; CheckedBy: Not used; Author: Not used; CompanyName: STMicroelectronics; DrawnBy: Not used; Engineer: Not used; Organization: Not used; Address1: Not used; Address2: Not used; Address3: Not used; Address4: Not used; DocumentNumber: 5; Revision: Not used; SheetNumber: 5; SheetTotal: 7
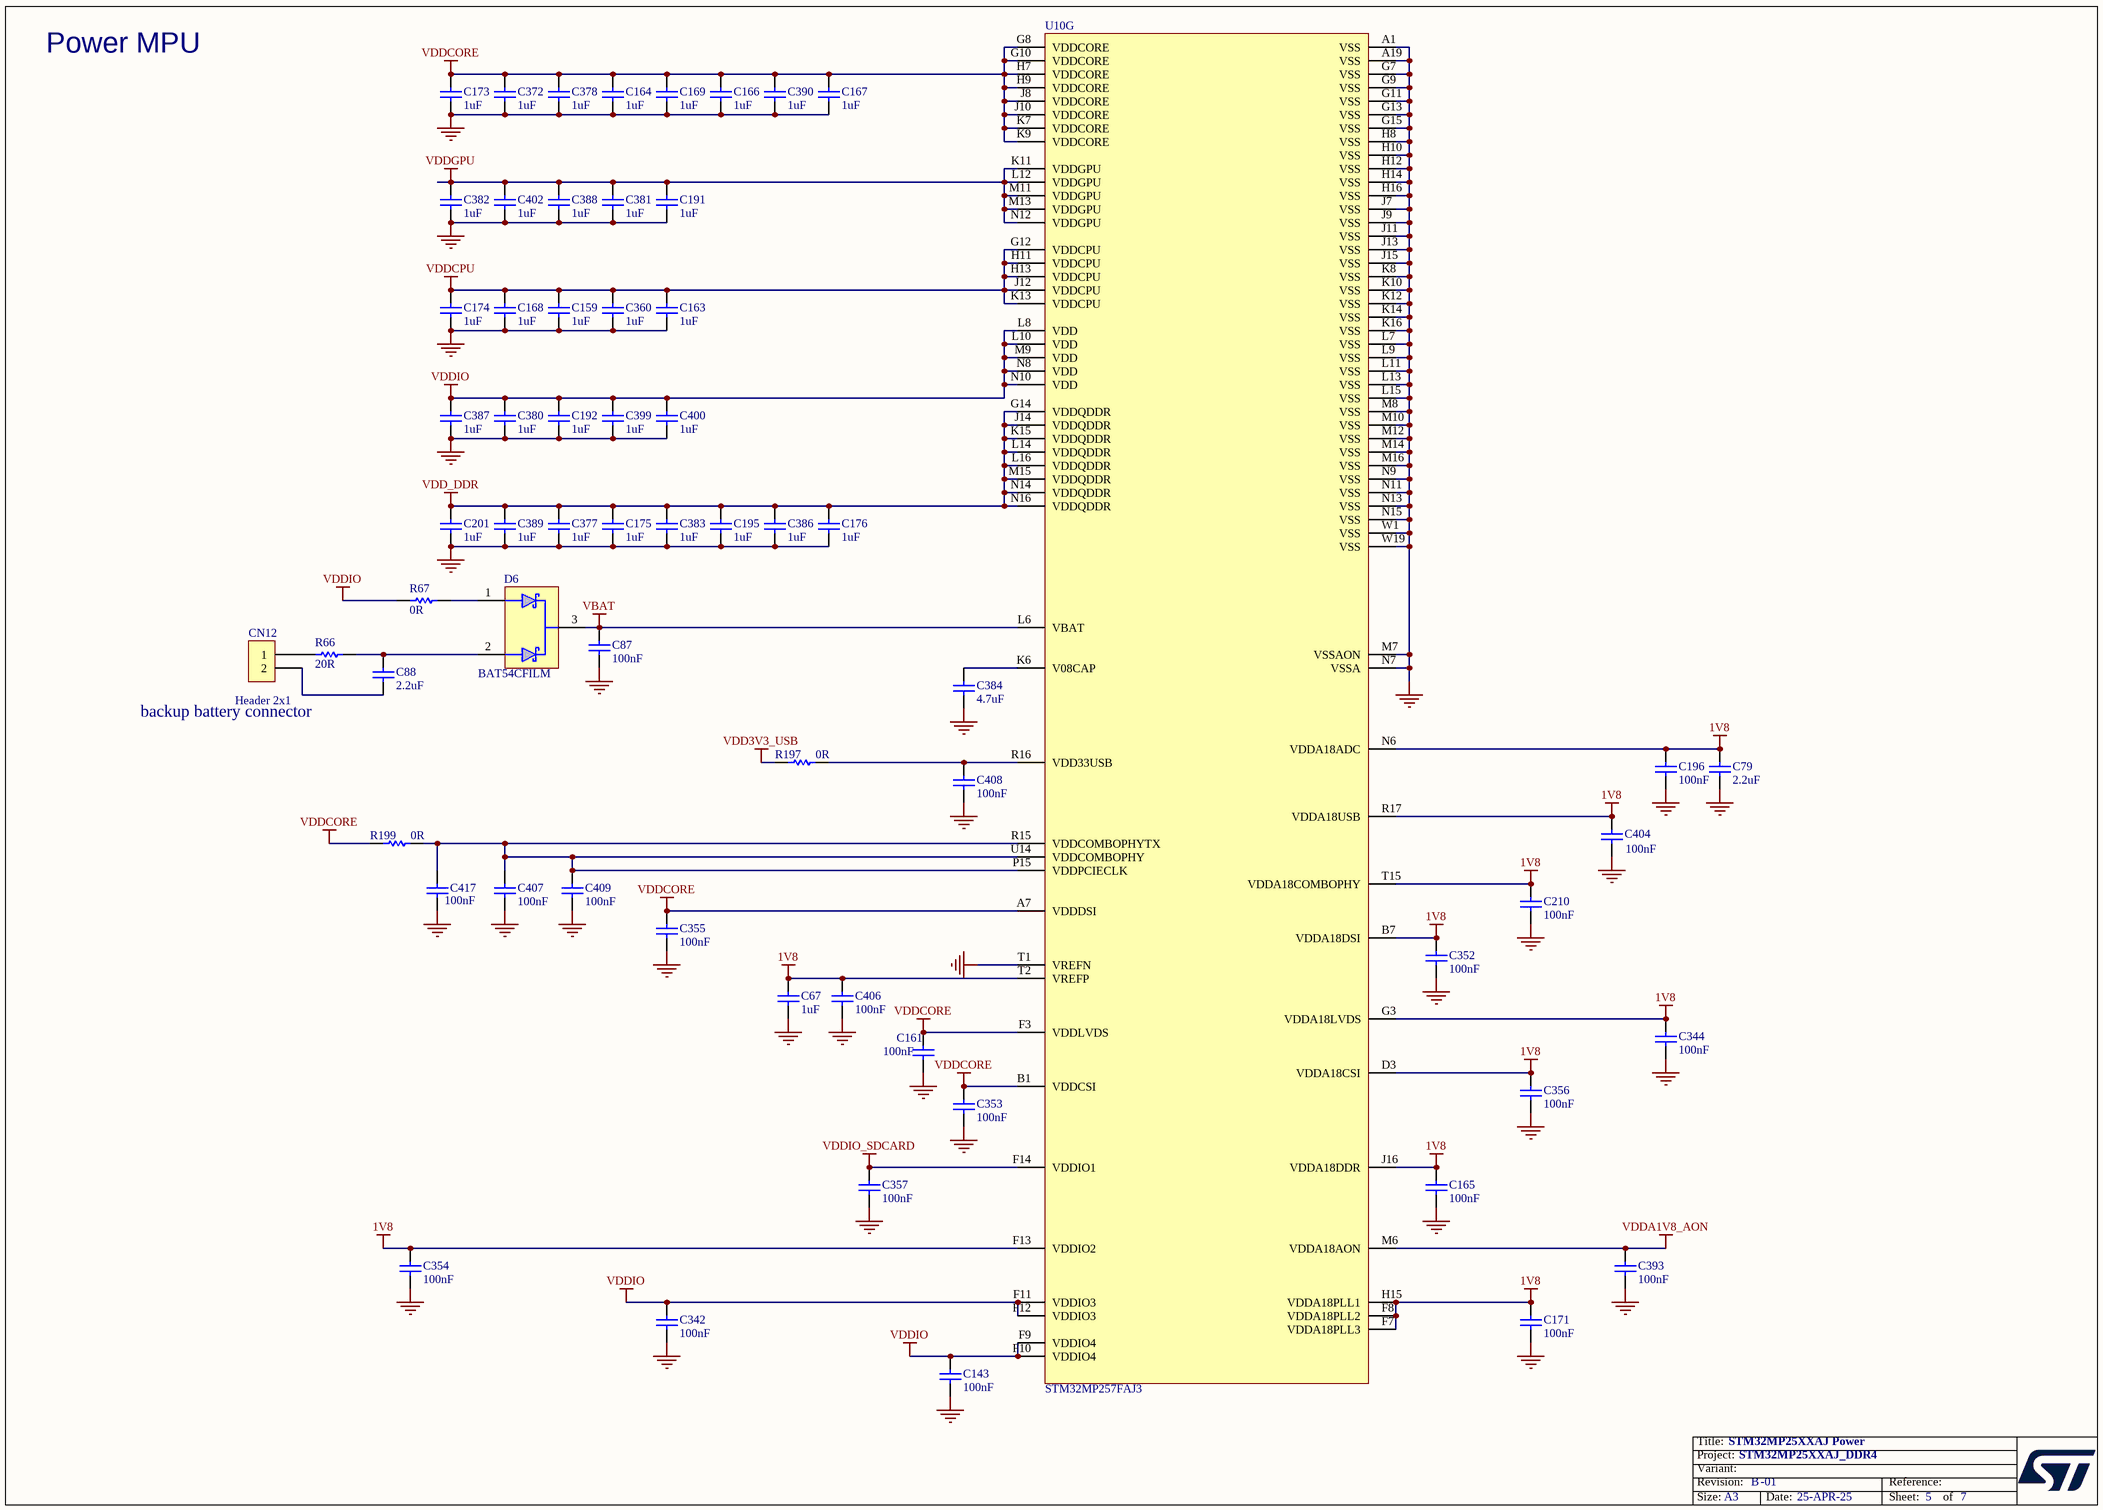
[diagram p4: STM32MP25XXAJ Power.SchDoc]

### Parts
C67  value 1uF  [C0201_MURATA_GRM033_H0P3]  (hidden comment: Capacitor)
C79  value 2.2uF  [C0201_H0P5]  (hidden comment: Capacitor)
C87  value 100nF  [C0402]
C88  value 2.2uF  [C0402]  (hidden comment: Capacitor)
C143  value 100nF  [C0201_MURATA_GRM033_H0P3]  (hidden comment: Capacitor)
C159  value 1uF  [C0201_MURATA_GRM033_H0P3]  (hidden comment: Capacitor)
C161  value 100nF  [C0201_MURATA_GRM033_H0P3]  (hidden comment: Capacitor)
C163  value 1uF  [C0201_MURATA_GRM033_H0P3]  (hidden comment: Capacitor)
C164  value 1uF  [C0201_MURATA_GRM033_H0P3]  (hidden comment: Capacitor)
C165  value 100nF  [C0201_MURATA_GRM033_H0P3]  (hidden comment: Capacitor)
C166  value 1uF  [C0201_MURATA_GRM033_H0P3]  (hidden comment: Capacitor)
C167  value 1uF  [C0201_MURATA_GRM033_H0P3]  (hidden comment: Capacitor)
C168  value 1uF  [C0201_MURATA_GRM033_H0P3]  (hidden comment: Capacitor)
C169  value 1uF  [C0201_MURATA_GRM033_H0P3]  (hidden comment: Capacitor)
C171  value 100nF  [C0201_MURATA_GRM033_H0P3]  (hidden comment: Capacitor)
C173  value 1uF  [C0201_MURATA_GRM033_H0P3]  (hidden comment: Capacitor)
C174  value 1uF  [C0201_MURATA_GRM033_H0P3]  (hidden comment: Capacitor)
C175  value 1uF  [C0201_MURATA_GRM033_H0P3]  (hidden comment: Capacitor)
C176  value 1uF  [C0201_MURATA_GRM033_H0P3]  (hidden comment: Capacitor)
C191  value 1uF  [C0201_MURATA_GRM033_H0P3]  (hidden comment: Capacitor)
C192  value 1uF  [C0201_MURATA_GRM033_H0P3]  (hidden comment: Capacitor)
C195  value 1uF  [C0201_MURATA_GRM033_H0P3]  (hidden comment: Capacitor)
C196  value 100nF  [C0201_MURATA_GRM033_H0P3]  (hidden comment: Capacitor)
C201  value 1uF  [C0201_MURATA_GRM033_H0P3]  (hidden comment: Capacitor)
C210  value 100nF  [C0201_MURATA_GRM033_H0P3]  (hidden comment: Capacitor)
C342  value 100nF  [C0201_MURATA_GRM033_H0P3]  (hidden comment: Capacitor)
C344  value 100nF  [C0201_MURATA_GRM033_H0P3]  (hidden comment: Capacitor)
C352  value 100nF  [C0201_MURATA_GRM033_H0P3]  (hidden comment: Capacitor)
C353  value 100nF  [C0201_MURATA_GRM033_H0P3]  (hidden comment: Capacitor)
C354  value 100nF  [C0201_MURATA_GRM033_H0P3]  (hidden comment: Capacitor)
C355  value 100nF  [C0201_MURATA_GRM033_H0P3]  (hidden comment: Capacitor)
C356  value 100nF  [C0201_MURATA_GRM033_H0P3]  (hidden comment: Capacitor)
C357  value 100nF  [C0201_MURATA_GRM033_H0P3]  (hidden comment: Capacitor)
C360  value 1uF  [C0201_MURATA_GRM033_H0P3]  (hidden comment: Capacitor)
C372  value 1uF  [C0201_MURATA_GRM033_H0P3]  (hidden comment: Capacitor)
C377  value 1uF  [C0201_MURATA_GRM033_H0P3]  (hidden comment: Capacitor)
C378  value 1uF  [C0201_MURATA_GRM033_H0P3]  (hidden comment: Capacitor)
C380  value 1uF  [C0201_MURATA_GRM033_H0P3]  (hidden comment: Capacitor)
C381  value 1uF  [C0201_MURATA_GRM033_H0P3]  (hidden comment: Capacitor)
C382  value 1uF  [C0201_MURATA_GRM033_H0P3]  (hidden comment: Capacitor)
C383  value 1uF  [C0201_MURATA_GRM033_H0P3]  (hidden comment: Capacitor)
C384  value 4.7uF  [C0201_H0P5]  (hidden comment: Capacitor)
C386  value 1uF  [C0201_MURATA_GRM033_H0P3]  (hidden comment: Capacitor)
C387  value 1uF  [C0201_MURATA_GRM033_H0P3]  (hidden comment: Capacitor)
C388  value 1uF  [C0201_MURATA_GRM033_H0P3]  (hidden comment: Capacitor)
C389  value 1uF  [C0201_MURATA_GRM033_H0P3]  (hidden comment: Capacitor)
C390  value 1uF  [C0201_MURATA_GRM033_H0P3]  (hidden comment: Capacitor)
C393  value 100nF  [C0201_MURATA_GRM033_H0P3]  (hidden comment: Capacitor)
C399  value 1uF  [C0201_MURATA_GRM033_H0P3]  (hidden comment: Capacitor)
C400  value 1uF  [C0201_MURATA_GRM033_H0P3]  (hidden comment: Capacitor)
C402  value 1uF  [C0201_MURATA_GRM033_H0P3]  (hidden comment: Capacitor)
C404  value 100nF  [C0201_MURATA_GRM033_H0P3]  (hidden comment: Capacitor)
C406  value 100nF  [C0201_MURATA_GRM033_H0P3]  (hidden comment: Capacitor)
C407  value 100nF  [C0201_MURATA_GRM033_H0P3]  (hidden comment: Capacitor)
C408  value 100nF  [C0201_MURATA_GRM033_H0P3]  (hidden comment: Capacitor)
C409  value 100nF  [C0201_MURATA_GRM033_H0P3]  (hidden comment: Capacitor)
C417  value 100nF  [C0201_MURATA_GRM033_H0P3]  (hidden comment: Capacitor)
CN12  value Header 2x1  [CON_MOLEX_53047-0210]
D6  value BAT54CFILM  [DIO_SOT23]  (hidden comment: DIODE_3P_DUAL_COMMON_CATHODE)
R66  value 20R  [R0402]  (hidden comment: Resistor)
R67  value 0R  [R0402]  (hidden comment: Resistor)
R197  value 0R  [R0402]
R199  value 0R  [R0402]
U10  value STM32MP257FAJ3  [ICC_TFBGA361_16X16_P080]  (hidden comment: IC_STM32MP257FAJ3)  (part G of 9)

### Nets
1V8: C67.2 C79.2 C165.2 C171.2 C196.2 C210.2 C344.2 C352.2 C354.2 C356.2 C404.2 C406.2 U10.B7(VDDA18DSI) U10.D3(VDDA18CSI) U10.F7(VDDA18PLL3) U10.F8(VDDA18PLL2) U10.F13(VDDIO2) U10.G3(VDDA18LVDS) U10.H15(VDDA18PLL1) U10.J16(VDDA18DDR) U10.N6(VDDA18ADC) U10.R17(VDDA18USB) U10.T2(VREFP) U10.T15(VDDA18COMBOPHY)
GND: C67.1 C79.1 C87.1 C143.1 C159.1 C161.1 C163.1 C164.2 C165.1 C166.1 C167.1 C168.1 C169.1 C171.1 C173.2 C174.2 C175.1 C176.1 C191.2 C192.1 C195.1 C196.1 C201.1 C210.1 C342.1 C344.1 C352.1 C353.1 C354.1 C355.1 C356.1 C357.1 C360.2 C372.1 C377.1 C378.1 C380.1 C381.1 C382.1 C383.1 C384.1 C386.1 C387.2 C388.1 C389.2 C390.1 C393.1 C399.2 C400.1 C402.1 C404.1 C406.1 C407.1 C408.1 C409.1 C417.1 U10.A1(VSS) U10.A19(VSS) U10.G7(VSS) U10.G9(VSS) U10.G11(VSS) U10.G13(VSS) U10.G15(VSS) U10.H8(VSS) U10.H10(VSS) U10.H12(VSS) U10.H14(VSS) U10.H16(VSS) U10.J7(VSS) U10.J9(VSS) U10.J11(VSS) U10.J13(VSS) U10.J15(VSS) U10.K8(VSS) U10.K10(VSS) U10.K12(VSS) U10.K14(VSS) U10.K16(VSS) U10.L7(VSS) U10.L9(VSS) U10.L11(VSS) U10.L13(VSS) U10.L15(VSS) U10.M7(VSSAON) U10.M8(VSS) U10.M10(VSS) U10.M12(VSS) U10.M14(VSS) U10.M16(VSS) U10.N7(VSSA) U10.N9(VSS) U10.N11(VSS) U10.N13(VSS) U10.N15(VSS) U10.T1(VREFN) U10.W1(VSS) U10.W19(VSS)
VBAT: C87.2 D6.3 U10.L6(VBAT)
VDD3V3_USB: R197.1
VDD_DDR: C175.2 C176.2 C195.2 C201.2 C377.2 C383.2 C386.2 C389.1 U10.G14(VDDQDDR) U10.J14(VDDQDDR) U10.K15(VDDQDDR) U10.L14(VDDQDDR) U10.L16(VDDQDDR) U10.M15(VDDQDDR) U10.N14(VDDQDDR) U10.N16(VDDQDDR)
VDDA1V8_AON: C393.2 U10.M6(VDDA18AON)
VDDCORE: C161.2 C164.1 C166.2 C167.2 C169.2 C173.1 C353.2 C355.2 C372.2 C378.2 C390.2 R199.1 U10.A7(VDDDSI) U10.B1(VDDCSI) U10.F3(VDDLVDS) U10.G8(VDDCORE) U10.G10(VDDCORE) U10.H7(VDDCORE) U10.H9(VDDCORE) U10.J8(VDDCORE) U10.J10(VDDCORE) U10.K7(VDDCORE) U10.K9(VDDCORE)
VDDCPU: C159.2 C163.2 C168.2 C174.1 C360.1 U10.G12(VDDCPU) U10.H11(VDDCPU) U10.H13(VDDCPU) U10.J12(VDDCPU) U10.K13(VDDCPU)
VDDGPU: C191.1 C381.2 C382.2 C388.2 C402.2 U10.K11(VDDGPU) U10.L12(VDDGPU) U10.M11(VDDGPU) U10.M13(VDDGPU) U10.N12(VDDGPU)
VDDIO: C143.2 C192.2 C342.2 C380.2 C387.1 C399.1 C400.2 R67.2 U10.F9(VDDIO4) U10.F10(VDDIO4) U10.F11(VDDIO3) U10.F12(VDDIO3) U10.L8(VDD) U10.L10(VDD) U10.M9(VDD) U10.N8(VDD) U10.N10(VDD)
VDDIO_SDCARD: C357.2 U10.F14(VDDIO1)
NetC88_1: C88.1 CN12.2
NetC88_2: C88.2 D6.2 R66.2
NetC384_2: C384.2 U10.K6(V08CAP)
NetC407_2: C407.2 C409.2 C417.2 R199.2 U10.P15(VDDPCIECLK) U10.R15(VDDCOMBOPHYTX) U10.U14(VDDCOMBOPHY)
NetC408_2: C408.2 R197.2 U10.R16(VDD33USB)
NetCN12_1: CN12.1 R66.1
NetD6_1: D6.1 R67.1

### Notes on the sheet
- Power MPU
- backup battery connector

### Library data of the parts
C67 = MCD-02377: Capacitor, MLCC, 1uF, 6.3V, X5R, +/-20%, 0201, T=0,3mm; Manufacturer_Part_Number: GRM033R60J105MEA2; Manufacturer: MURATA; Part_Preference: Recommended; Order_Code_RS: 820-0643; Component_Country_Of_Origin: Japan°; ID: 4483; ShowFields: YES
C79 = MCD-02235: Capacitor, MLCC, 2.2uF, 10V, X5R,+/-10%, 0201, T=0.5mm; Part_Preference: Recommended; Manufacturer: MURATA; Manufacturer_Part_Number: GRM033R61A225KE47D; Order_Code_RS: NA; Component_Country_Of_Origin: Japan°°; ShowFields: YES; ID: 4335
C87 = MCD-00006: Capacitor,100nF,16V,X7R,10%,0402; Manufacturer_Part_Number: CC0402KRX7R7BB104; Manufacturer: YAGEO; Alternate_Manufacturer: MURATA; Alternate_Manufacturer_Part_Number: GCM155R71C104KA55D; Part_Preference: Recommended; Partial_Alternate_Internal_Part_Number: MCD-03299; Provided_By: SUBCO; Initial_Board_Reference: MB1274; Order_Code_RS: 9402047; Component_Country_Of_Origin: China; ID: 2474; ShowFields: YES
C88 = MCD-01823: Capacitor, MLCC, 2.2uF, 6V3, X5R,+/-10%, 0402, T=0.5mm; Part_Preference: Recommended; Manufacturer: MURATA; Manufacturer_Part_Number: GRM155R60J225KE95D; Partial_Alternate_Internal_Part_Number: MCD-03566; Order_Code_RS: 172-6478; Component_Country_Of_Origin: Japan°°; ID: 3923; ShowFields: YES
C143 C161 C165 C171 C196 C210 C342 C344 C352-C357 C393 C404 C406-C409 C417 = MCD-01535: Capacitor, MLCC,100nF, 10V, X7R, +/-10%, 0201, T=0.3mm; Part_Preference: Recommended; Manufacturer: MURATA; Manufacturer_Part_Number: GRM033R61A104KE15; Order_Code_RS: 790-2742
C159 C163 C164 C166-C169 C173-C176 C191 C192 C195 C201 C360 C372 C377 C378 C380-C383 C386-C390 C399 C400 C402 = MCD-02377: Capacitor, MLCC, 1uF, 6.3V, X5R, +/-20%, 0201, T=0,3mm; Manufacturer_Part_Number: GRM033R60J105MEA2; Manufacturer: MURATA; Part_Preference: Recommended; Order_Code_RS: 820-0643
C384 = MCD-01534: Capacitor, MLCC, 4,7uF, 6V3, X5R, +/-20%, 0201, T=0.5mm; Part_Preference: Recommended; Manufacturer: MURATA; Manufacturer_Part_Number: GRM035R60J475ME15
CN12 = MCD-00655: Header 2 circuits, 1.25mm Pitch ,  Vertical, with Friction Lock; Part_Type: Connector; Manufacturer_Part_Number: 53047-0210; Manufacturer: MOLEX; BMS_Part_Number: 9083002; Part_Preference: Recommended; Provided_By: SUBCO; Initial_Board_Reference: MB1272; Order_Code_RS: 279-9213; Component_Country_Of_Origin: Unknown; ID: 3091; ShowFields: YES
D6 = MCD-03280: Diode, Schottky, Dual Common Cathode, 0V3, 300mA, 40V, SOT-23; Part_Preference: Recommended; Manufacturer: STMICROELECTRONICS; Order_code_RS: 795-8397; Component_Country_Of_Origin: China; ShowFields: YES; ID: 5396
R66 = MCD-00058: Resistor, 20R, 0402, +/-1%, 1/16W; BMS_Part_Number: 9131027; Part_Preference: Recommended; Manufacturer: YAGEO; Manufacturer_Part_Number: RC0402FR-0720RL; Order_Code_RS: 1799192; Component_Country_Of_Origin: China; ID: 2537; ShowFields: YES
R67 = MCD-00052: Resistor, 0R, 0402, +/-5%, 1/16W; Manufacturer_Part_Number: RC0402JR-070RL; Manufacturer: YAGEO; Part_Preference: Recommended; Order_Code_RS: 9232516RL; Component_Country_Of_Origin: China; ShowFields: YES; ID: 2540
R197 R199 = MCD-00052: Resistor,0R,0402,5%,1/16W; Manufacturer_Part_Number: RC0402JR-070RL; Manufacturer: YAGEO; Part_Preference: Recommended; ECCN_US: EAR99; ECCN_EU: NEC; Provided_By: SUBCO; Initial_Board_Reference: mb1274; Order_Code_RS: 618-5804
U10 = MCD-04441: as U10 on sheet STM32MP25XXAJ I_Os

## Sheet eMMC.SchDoc: eMMC
size A3; Date: Not used; ApprovedBy: Not used; CheckedBy: Not used; Author: Not used; CompanyName: STMicroelectronics; DrawnBy: Not used; Engineer: Not used; Organization: Not used; Address1: Not used; Address2: Not used; Address3: Not used; Address4: Not used; DocumentNumber: 7; Revision: Not used; SheetNumber: 7; SheetTotal: 7
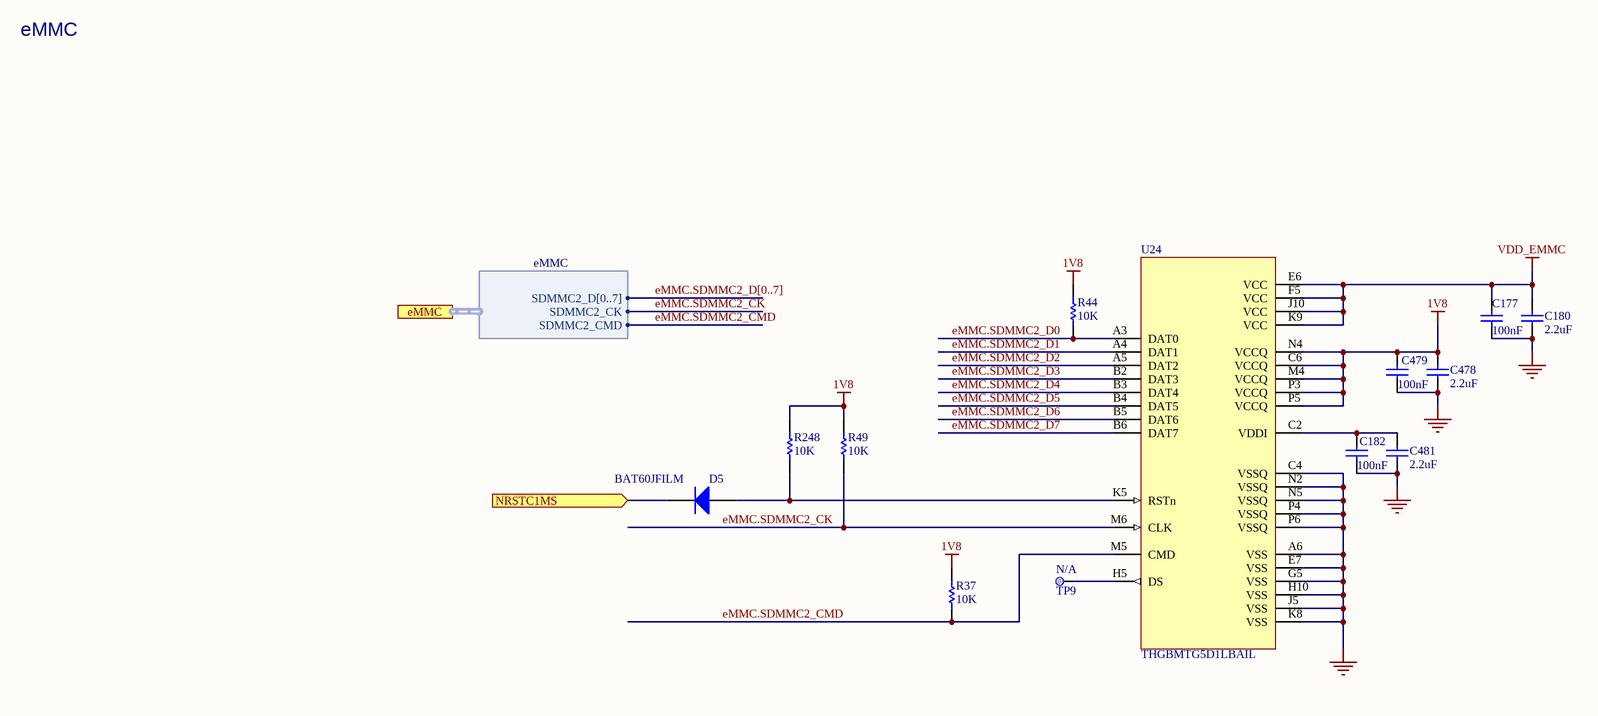
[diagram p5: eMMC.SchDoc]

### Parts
C177  value 100nF  [C0402]  (hidden comment: Capacitor)
C180  value 2.2uF  [C0402]  (hidden comment: Capacitor)
C182  value 100nF  [C0402]  (hidden comment: Capacitor)
C478  value 2.2uF  [C0402]  (hidden comment: Capacitor)
C479  value 100nF  [C0402]  (hidden comment: Capacitor)
C481  value 2.2uF  [C0402]  (hidden comment: Capacitor)
D5  BAT60JFILM  [DIO_SOD323]
R37  value 10K  [R0402]  (hidden comment: Resistor)
R44  value 10K  [R0402]  (hidden comment: Resistor)
R49  value 10K  [R0402]  (hidden comment: Resistor)
R248  value 10K  [R0402]  (hidden comment: Resistor)
TP9  Test Point  [TP_SMD_1MM]  (value not drawn)  (no BOM)
U24  value THGBMTG5D1LBAIL  [ICC_P-WFBGA153_13X11P5_P050]  (hidden comment: eMMC_THGBMTG5D1LBAIL)

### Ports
eMMC (harness eMMC), NRSTC1MS (in)

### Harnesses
eMMC: SDMMC2_CK, SDMMC2_CMD, SDMMC2_D[0..7]

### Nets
1V8: C478.2 C479.2 R37.2 R44.2 R49.2 R248.2 U24.C6(VCCQ) U24.M4(VCCQ) U24.N4(VCCQ) U24.P3(VCCQ) U24.P5(VCCQ)
GND: C177.1 C180.1 C182.1 C478.1 C479.1 C481.1 U24.A6(VSS) U24.C4(VSSQ) U24.E7(VSS) U24.G5(VSS) U24.H10(VSS) U24.J5(VSS) U24.K8(VSS) U24.N2(VSSQ) U24.N5(VSSQ) U24.P4(VSSQ) U24.P6(VSSQ)
VDD_EMMC: C177.2 C180.2 U24.E6(VCC) U24.F5(VCC) U24.J10(VCC) U24.K9(VCC)
eMMC.SDMMC2_CK: R49.1 U24.M6(CLK) ; port eMMC.SDMMC2_CK
eMMC.SDMMC2_CMD: R37.1 U24.M5(CMD) ; port eMMC.SDMMC2_CMD
eMMC.SDMMC2_D0: R44.1 U24.A3(DAT0)
eMMC.SDMMC2_D1: U24.A4(DAT1)
eMMC.SDMMC2_D2: U24.A5(DAT2)
eMMC.SDMMC2_D3: U24.B2(DAT3)
eMMC.SDMMC2_D4: U24.B3(DAT4)
eMMC.SDMMC2_D5: U24.B4(DAT5)
eMMC.SDMMC2_D6: U24.B5(DAT6)
eMMC.SDMMC2_D7: U24.B6(DAT7)
NRSTC1MS: D5.2(K) ; port NRSTC1MS
NetC182_2: C182.2 C481.2 U24.C2(VDDI)
NetD5_1: D5.1(A) R248.1 U24.K5(RSTn)
NetTP9_1: TP9.1 U24.H5(DS)

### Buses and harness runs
bus eMMC.SDMMC2_D[0..7]

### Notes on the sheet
- eMMC

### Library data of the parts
C177 C182 C479 = MCD-00006: Capacitor, MLCC, 100nF, 16V, X7R, +/-10%, 0402, T=0.5mm; Part_Preference: Recommended; Manufacturer: YAGEO; Manufacturer_Part_Number: CC0402KRX7R7BB104; Alternate_Manufacturer: MURATA; Alternate_Manufacturer_Part_Number: GCM155R71C104KA55D; Partial_Alternate_Internal_Part_Number: MCD-03299; Order_Code_RS: 9402047; Component_Country_Of_Origin: China; ID: 2474; ShowFields: YES
C180 C478 C481 = MCD-02606: Capacitor, MLCC, 2.2uF, 6.3V, X5R, +/-10%, 0402, T=0.5mm; Part_Preference: Recommended; Manufacturer: YAGEO; Manufacturer_Part_Number: CC0402KRX5R5BB225; Order_Code_RS: 1992205; ShowFields: YES; ID: 4712; Component_Country_Of_Origin: China°
D5 = MCD-00034: BMS_Part_Number: 9151097; Part_Type: Diode; Part_Preference: Recommended; Manufacturer: STMICROELECTRONICS; Manufacturer_HQ_COO: EU; Component_Country_Of_Origin: China; ShowFields: YES; ID: 2483; Order_Code_RS: 714-6879
R37 R44 R49 R248 = MCD-00053: Resistor,10K,0402,1%,1/16W; Manufacturer_Part_Number: RC0402FR-0710KL; Manufacturer: YAGEO; BMS_Part_Number: 9131590; Part_Preference: Recommended; ECCN_US: EAR99; ECCN_EU: NEC; Provided_By: SUBCO; Order_Code_RS: 9239359; Component_Country_Of_Origin: China; ID: 2539; ShowFields: YES
TP9 = MCD-00074: Test Point 1mm; Part_Type: Misc; Part_Preference: Recommended; Component_Country_Of_Origin: Unknown; ID: 2518; ShowFields: YES
U24 = MCD-02799: Memory, eMMC, 4GB, 15nm ,WFBGA , 153 pins; Part_Type: IC; Part_Preference: Not recommended; Manufacturer: KIOXIA; ShowFields: YES; ID: 4911; Component_Country_Of_Origin: Unknown

## Sheet DDR4_16bits.SchDoc: DDR4_16bits
size A3; Date: Not used; ApprovedBy: Not used; CheckedBy: Not used; Author: Not used; CompanyName: STMicroelectronics; DrawnBy: Not used; Engineer: Not used; Organization: Not used; Address1: Not used; Address2: Not used; Address3: Not used; Address4: Not used; DocumentNumber: 6; Revision: Not used; SheetNumber: 6; SheetTotal: 7
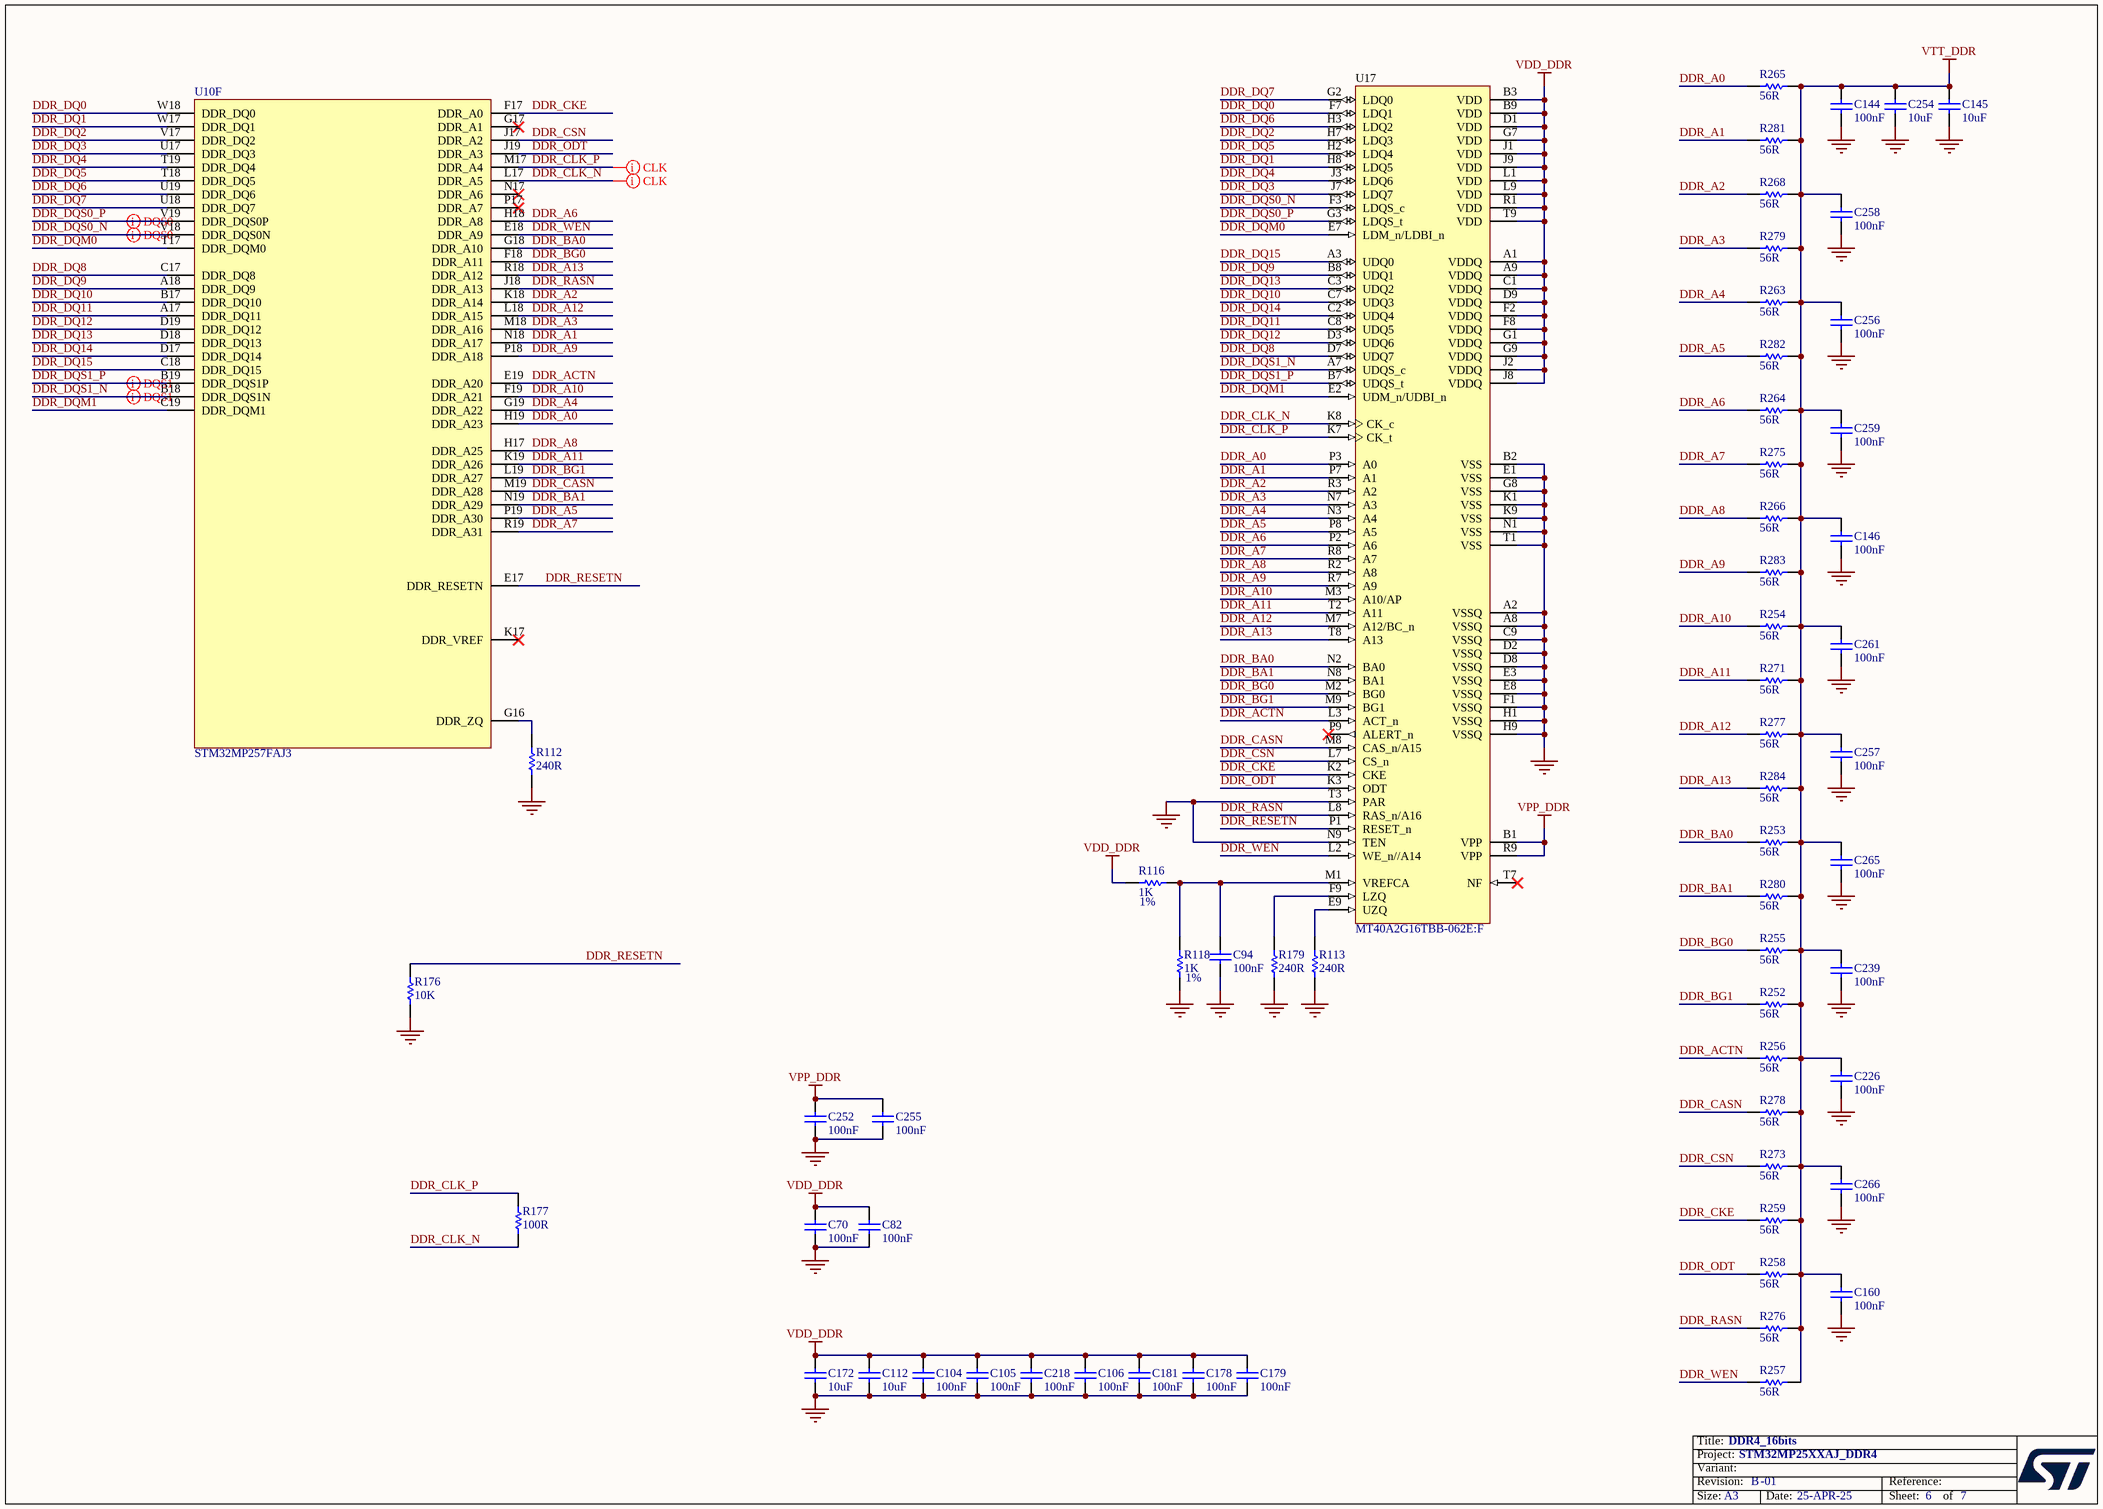
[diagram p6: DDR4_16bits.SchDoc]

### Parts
C70  value 100nF  [C0402]  (hidden comment: Capacitor)
C82  value 100nF  [C0402]  (hidden comment: Capacitor)
C94  value 100nF  [C0402]  (hidden comment: Capacitor)
C104  value 100nF  [C0402]  (hidden comment: Capacitor)
C105  value 100nF  [C0402]  (hidden comment: Capacitor)
C106  value 100nF  [C0402]  (hidden comment: Capacitor)
C112  value 10uF  [C0603]  (hidden comment: Capacitor)
C144  value 100nF  [C0402]  (hidden comment: Capacitor)
C145  value 10uF  [C0402]  (hidden comment: Capacitor)
C146  value 100nF  [C0402]  (hidden comment: Capacitor)
C160  value 100nF  [C0402]  (hidden comment: Capacitor)
C172  value 10uF  [C0603]  (hidden comment: Capacitor)
C178  value 100nF  [C0402]  (hidden comment: Capacitor)
C179  value 100nF  [C0402]  (hidden comment: Capacitor)
C181  value 100nF  [C0402]  (hidden comment: Capacitor)
C218  value 100nF  [C0402]  (hidden comment: Capacitor)
C226  value 100nF  [C0402]  (hidden comment: Capacitor)
C239  value 100nF  [C0402]  (hidden comment: Capacitor)
C252  value 100nF  [C0402]  (hidden comment: Capacitor)
C254  value 10uF  [C0402]  (hidden comment: Capacitor)
C255  value 100nF  [C0402]  (hidden comment: Capacitor)
C256  value 100nF  [C0402]  (hidden comment: Capacitor)
C257  value 100nF  [C0402]  (hidden comment: Capacitor)
C258  value 100nF  [C0402]  (hidden comment: Capacitor)
C259  value 100nF  [C0402]  (hidden comment: Capacitor)
C261  value 100nF  [C0402]  (hidden comment: Capacitor)
C265  value 100nF  [C0402]  (hidden comment: Capacitor)
C266  value 100nF  [C0402]  (hidden comment: Capacitor)
R112  value 240R  [R0201_H0P23]  (hidden comment: Resistor)
R113  value 240R  [R0201_H0P23]  (hidden comment: Resistor)
R116  value 1K  [R0402]  (hidden comment: Resistor)
R118  value 1K  [R0402]  (hidden comment: Resistor)
R176  value 10K  [R0402]  (hidden comment: Resistor)
R177  value 100R  [R0402]  (hidden comment: Resistor)
R179  value 240R  [R0201_H0P23]  (hidden comment: Resistor)
R252  value 56R  [R0402]  (hidden comment: Resistor)
R253  value 56R  [R0402]  (hidden comment: Resistor)
R254  value 56R  [R0402]  (hidden comment: Resistor)
R255  value 56R  [R0402]  (hidden comment: Resistor)
R256  value 56R  [R0402]  (hidden comment: Resistor)
R257  value 56R  [R0402]  (hidden comment: Resistor)
R258  value 56R  [R0402]  (hidden comment: Resistor)
R259  value 56R  [R0402]  (hidden comment: Resistor)
R263  value 56R  [R0402]  (hidden comment: Resistor)
R264  value 56R  [R0402]  (hidden comment: Resistor)
R265  value 56R  [R0402]  (hidden comment: Resistor)
R266  value 56R  [R0402]  (hidden comment: Resistor)
R268  value 56R  [R0402]  (hidden comment: Resistor)
R271  value 56R  [R0402]  (hidden comment: Resistor)
R273  value 56R  [R0402]  (hidden comment: Resistor)
R275  value 56R  [R0402]  (hidden comment: Resistor)
R276  value 56R  [R0402]  (hidden comment: Resistor)
R277  value 56R  [R0402]  (hidden comment: Resistor)
R278  value 56R  [R0402]  (hidden comment: Resistor)
R279  value 56R  [R0402]  (hidden comment: Resistor)
R280  value 56R  [R0402]  (hidden comment: Resistor)
R281  value 56R  [R0402]  (hidden comment: Resistor)
R282  value 56R  [R0402]  (hidden comment: Resistor)
R283  value 56R  [R0402]  (hidden comment: Resistor)
R284  value 56R  [R0402]  (hidden comment: Resistor)
U10  value STM32MP257FAJ3  [ICC_TFBGA361_16X16_P080]  (hidden comment: IC_STM32MP257FAJ3)  (part F of 9)
U17  MT40A2G16TBB-062E:F  [ICC_FBGA96_TBB_7P5X13_P080]

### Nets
GND: C70.1 C82.1 C94.1 C104.1 C105.1 C106.1 C112.1 C144.1 C145.1 C146.1 C160.1 C172.1 C178.1 C179.1 C181.1 C218.1 C226.1 C239.1 C252.1 C254.1 C255.1 C256.1 C257.1 C258.1 C259.1 C261.1 C265.1 C266.1 R112.1 R113.1 R118.1 R176.1 R179.1 U17.A2(VSSQ) U17.A8(VSSQ) U17.B2(VSS) U17.C9(VSSQ) U17.D2(VSSQ) U17.D8(VSSQ) U17.E1(VSS) U17.E3(VSSQ) U17.E8(VSSQ) U17.F1(VSSQ) U17.G8(VSS) U17.H1(VSSQ) U17.H9(VSSQ) U17.K1(VSS) U17.K9(VSS) U17.N1(VSS) U17.N9(TEN) U17.T1(VSS) U17.T3(PAR)
VDD_DDR: C70.2 C82.2 C104.2 C105.2 C106.2 C112.2 C172.2 C178.2 C179.2 C181.2 C218.2 R116.1 U17.A1(VDDQ) U17.A9(VDDQ) U17.B3(VDD) U17.B9(VDD) U17.C1(VDDQ) U17.D1(VDD) U17.D9(VDDQ) U17.F2(VDDQ) U17.F8(VDDQ) U17.G1(VDDQ) U17.G7(VDD) U17.G9(VDDQ) U17.J1(VDD) U17.J2(VDDQ) U17.J8(VDDQ) U17.J9(VDD) U17.L1(VDD) U17.L9(VDD) U17.R1(VDD) U17.T9(VDD)
VPP_DDR: C252.2 C255.2 U17.B1(VPP) U17.R9(VPP)
VTT_DDR: C144.2 C145.2 C146.2 C160.2 C226.2 C239.2 C254.2 C256.2 C257.2 C258.2 C259.2 C261.2 C265.2 C266.2 R252.2 R253.2 R254.2 R255.2 R256.2 R257.2 R258.2 R259.2 R263.2 R264.2 R265.2 R266.2 R268.2 R271.2 R273.2 R275.2 R276.2 R277.2 R278.2 R279.2 R280.2 R281.2 R282.2 R283.2 R284.2
DDR_A0: R265.1 U10.H19(DDR_A23) U17.P3(A0)
DDR_A1: R281.1 U10.N18(DDR_A17) U17.P7(A1)
DDR_A2: R268.1 U10.K18(DDR_A14) U17.R3(A2)
DDR_A3: R279.1 U10.M18(DDR_A16) U17.N7(A3)
DDR_A4: R263.1 U10.G19(DDR_A22) U17.N3(A4)
DDR_A5: R282.1 U10.P19(DDR_A30) U17.P8(A5)
DDR_A6: R264.1 U10.H18(DDR_A8) U17.P2(A6)
DDR_A7: R275.1 U10.R19(DDR_A31) U17.R8(A7)
DDR_A8: R266.1 U10.H17(DDR_A25) U17.R2(A8)
DDR_A9: R283.1 U10.P18(DDR_A18) U17.R7(A9)
DDR_A10: R254.1 U10.F19(DDR_A21) U17.M3(A10/AP)
DDR_A11: R271.1 U10.K19(DDR_A26) U17.T2(A11)
DDR_A12: R277.1 U10.L18(DDR_A15) U17.M7(A12/BC_n)
DDR_A13: R284.1 U10.R18(DDR_A12) U17.T8(A13)
DDR_ACTN: R256.1 U10.E19(DDR_A20) U17.L3(ACT_n)
DDR_BA0: R253.1 U10.G18(DDR_A10) U17.N2(BA0)
DDR_BA1: R280.1 U10.N19(DDR_A29) U17.N8(BA1)
DDR_BG0: R255.1 U10.F18(DDR_A11) U17.M2(BG0)
DDR_BG1: R252.1 U10.L19(DDR_A27) U17.M9(BG1)
DDR_CASN: R278.1 U10.M19(DDR_A28) U17.M8(CAS_n/A15)
DDR_CKE: R259.1 U10.F17(DDR_A0) U17.K2(CKE)
DDR_CLK_N: R177.2 U10.L17(DDR_A5) U17.K8(CK_c)
DDR_CLK_P: R177.1 U10.M17(DDR_A4) U17.K7(CK_t)
DDR_CSN: R273.1 U10.J17(DDR_A2) U17.L7(CS_n)
DDR_DQ0: U10.W18(DDR_DQ0) U17.F7(LDQ1)
DDR_DQ1: U10.W17(DDR_DQ1) U17.H8(LDQ5)
DDR_DQ2: U10.V17(DDR_DQ2) U17.H7(LDQ3)
DDR_DQ3: U10.U17(DDR_DQ3) U17.J7(LDQ7)
DDR_DQ4: U10.T19(DDR_DQ4) U17.J3(LDQ6)
DDR_DQ5: U10.T18(DDR_DQ5) U17.H2(LDQ4)
DDR_DQ6: U10.U19(DDR_DQ6) U17.H3(LDQ2)
DDR_DQ7: U10.U18(DDR_DQ7) U17.G2(LDQ0)
DDR_DQ8: U10.C17(DDR_DQ8) U17.D7(UDQ7)
DDR_DQ9: U10.A18(DDR_DQ9) U17.B8(UDQ1)
DDR_DQ10: U10.B17(DDR_DQ10) U17.C7(UDQ3)
DDR_DQ11: U10.A17(DDR_DQ11) U17.C8(UDQ5)
DDR_DQ12: U10.D19(DDR_DQ12) U17.D3(UDQ6)
DDR_DQ13: U10.D18(DDR_DQ13) U17.C3(UDQ2)
DDR_DQ14: U10.D17(DDR_DQ14) U17.C2(UDQ4)
DDR_DQ15: U10.C18(DDR_DQ15) U17.A3(UDQ0)
DDR_DQM0: U10.T17(DDR_DQM0) U17.E7(LDM_n/LDBI_n)
DDR_DQM1: U10.C19(DDR_DQM1) U17.E2(UDM_n/UDBI_n)
DDR_DQS0_N: U10.V18(DDR_DQS0N) U17.F3(LDQS_c)
DDR_DQS0_P: U10.V19(DDR_DQS0P) U17.G3(LDQS_t)
DDR_DQS1_N: U10.B18(DDR_DQS1N) U17.A7(UDQS_c)
DDR_DQS1_P: U10.B19(DDR_DQS1P) U17.B7(UDQS_t)
DDR_ODT: R258.1 U10.J19(DDR_A3) U17.K3(ODT)
DDR_RASN: R276.1 U10.J18(DDR_A13) U17.L8(RAS_n/A16)
DDR_RESETN: R176.2 U10.E17(DDR_RESETN) U17.P1(RESET_n)
DDR_WEN: R257.1 U10.E18(DDR_A9) U17.L2(WE_n//A14)
NetC94_2: C94.2 R116.2 R118.2 U17.M1(VREFCA)
NetR112_2: R112.2 U10.G16(DDR_ZQ)
NetR113_2: R113.2 U17.E9(UZQ)
NetR179_2: R179.2 U17.F9(LZQ)

Not connected (* = marked no-connect by the designer): U10 G17(DDR_A1)* K17(DDR_VREF)* N17(DDR_A6)* P17(DDR_A7)*; U17 P9(ALERT_n)* T7(NF)*

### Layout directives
differential pair: DDR_CLK_N, DDR_CLK_P, DDR_DQS0_N, DDR_DQS0_P, DDR_DQS1_N, DDR_DQS1_P

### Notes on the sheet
- (near R116) 1%
- (near R118) 1%

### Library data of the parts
C70 C82 C94 C104-C106 C144 C146 C160 C178 C179 C181 C218 C226 C239 C252 C255-C259 C261 C265 C266 = MCD-00006: Capacitor, MLCC, 100nF, 16V, X7R, +/-10%, 0402, T=0.5mm; Part_Preference: Recommended; Manufacturer: YAGEO; Manufacturer_Part_Number: CC0402KRX7R7BB104; Alternate_Manufacturer: MURATA; Alternate_Manufacturer_Part_Number: GCM155R71C104KA55D; Order_Code_RS: 616-9701
C112 C172 = MCD-01341: Capacitor, MLCC, 10uF, 6V3, X5R, +/-20%, 0603, T=0,8mm; Part_Preference: Recommended; Manufacturer: MURATA; Manufacturer_Part_Number: GRM188R60J106ME47D; Alternate_Manufacturer_Part_Number: GRM188R60J106ME84D
C145 C254 = MCD-03140: as C39 on sheet PMIC
R112 R113 R179 = MCD-02253: Resistor,240R,0201,1%,1/20W; Part_Preference: Recommended; Manufacturer: YAGEO; Manufacturer_Part_Number: RC0201FR-07240RL
R116 R118 = MCD-00061: Resistor, 1K, 0402, +/-1%,1/16W; Part_Preference: Recommended; Manufacturer: YAGEO; Manufacturer_Part_Number: RC0402FR-071KL; Order_Code_RS: 9239235; Component_Country_Of_Origin: China; ShowFields: YES; ID: 2532
R176 = MCD-00053: Resistor,10K,0402,1%,1/16W; BMS_Part_Number: 9131590; Part_Preference: Recommended; Manufacturer: YAGEO; Manufacturer_Part_Number: RC0402FR-0710KL
R177 = MCD-01819: Resistor,100R,0402,0,5%,1/16W,±100ppm/°C; Part_Preference: Recommended; Manufacturer: YAGEO; Manufacturer_Part_Number: RC0402DR-07100RL
R252-R259 R263-R266 R268 R271 R273 R275-R284 = MCD-00054: Resistor, 56R, 0402, +/-1%, 1/16W; Part_Preference: Recommended; Manufacturer: YAGEO; Manufacturer_Part_Number: RC0402FR-0756RL
U10 = MCD-04441: as U10 on sheet STM32MP25XXAJ I_Os
U17 = MCD-04020: Memory, DDR4 SDRAM, 1V2, 32Gbit, 1.6GHz, FBGA96; Part_Type: IC; Part_Preference: Recommended; Manufacturer: MICRON; ShowFields: YES; ID: 6136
